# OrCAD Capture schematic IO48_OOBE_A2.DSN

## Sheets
1 01. Title: title: HPS IO48 OOBE Daughter Card; rev: A2; note: 150-0330632-A2     (6XX-44479R)
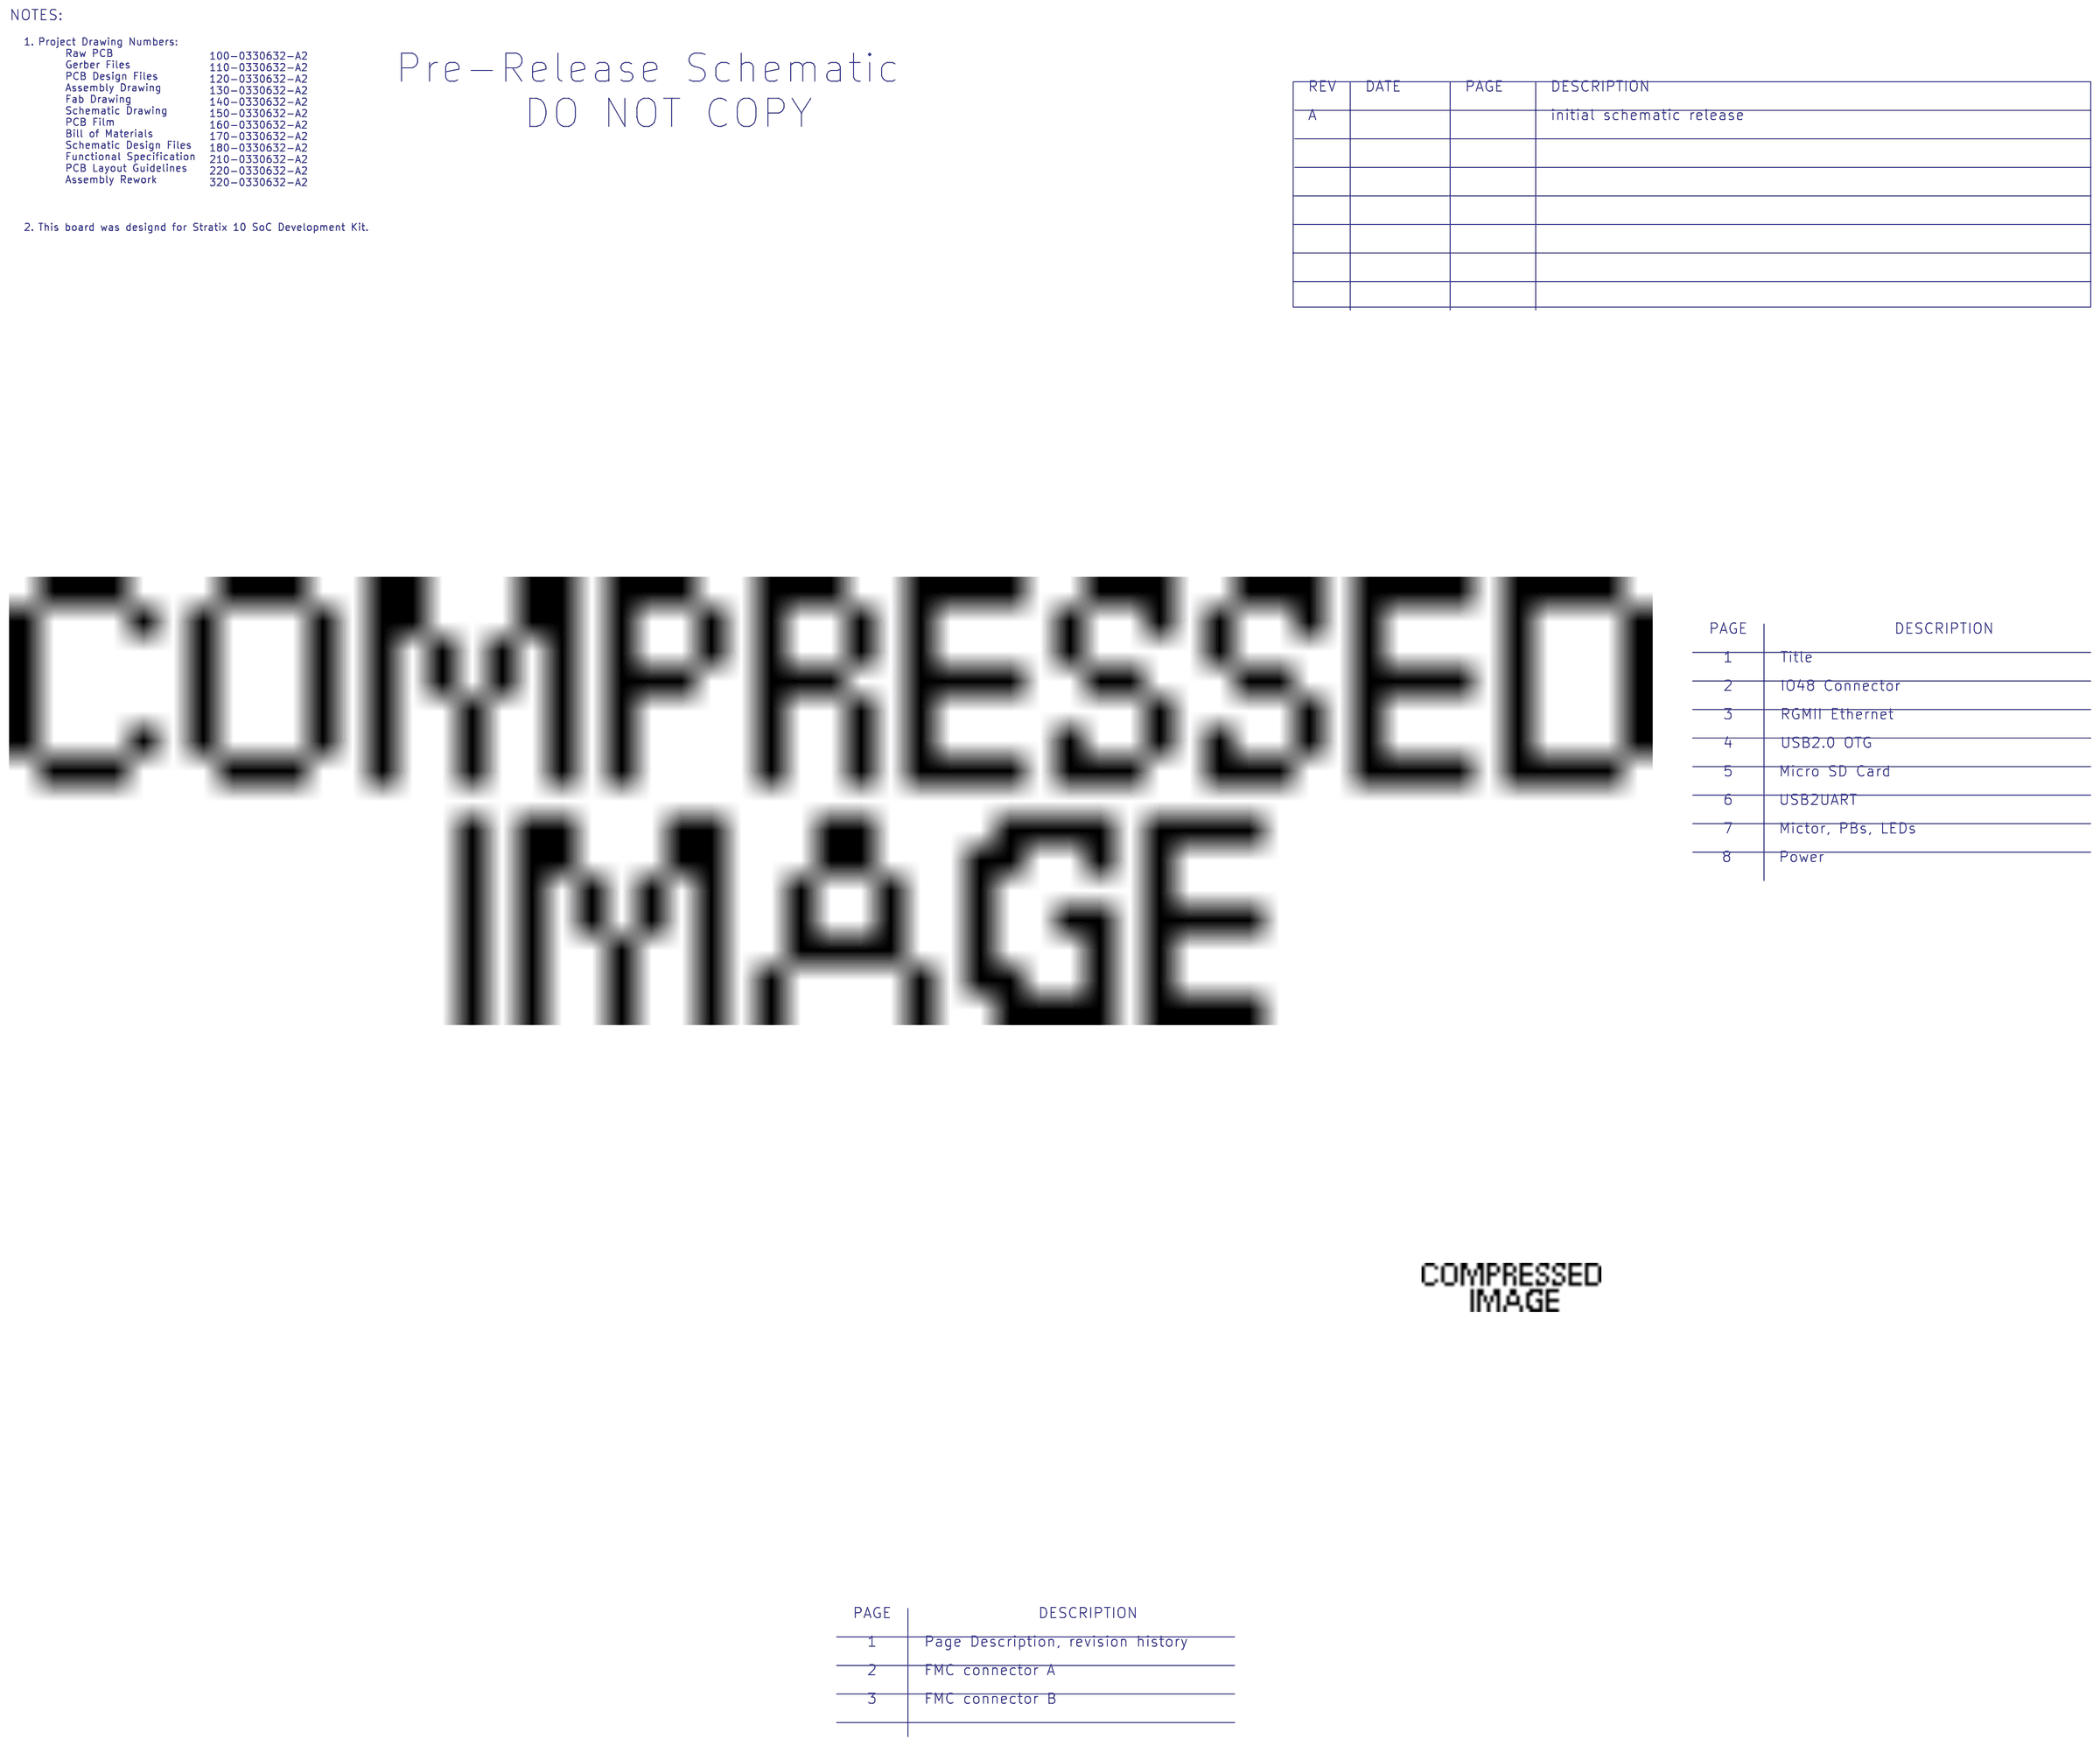
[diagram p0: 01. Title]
2 02. IO48 Connector: size B
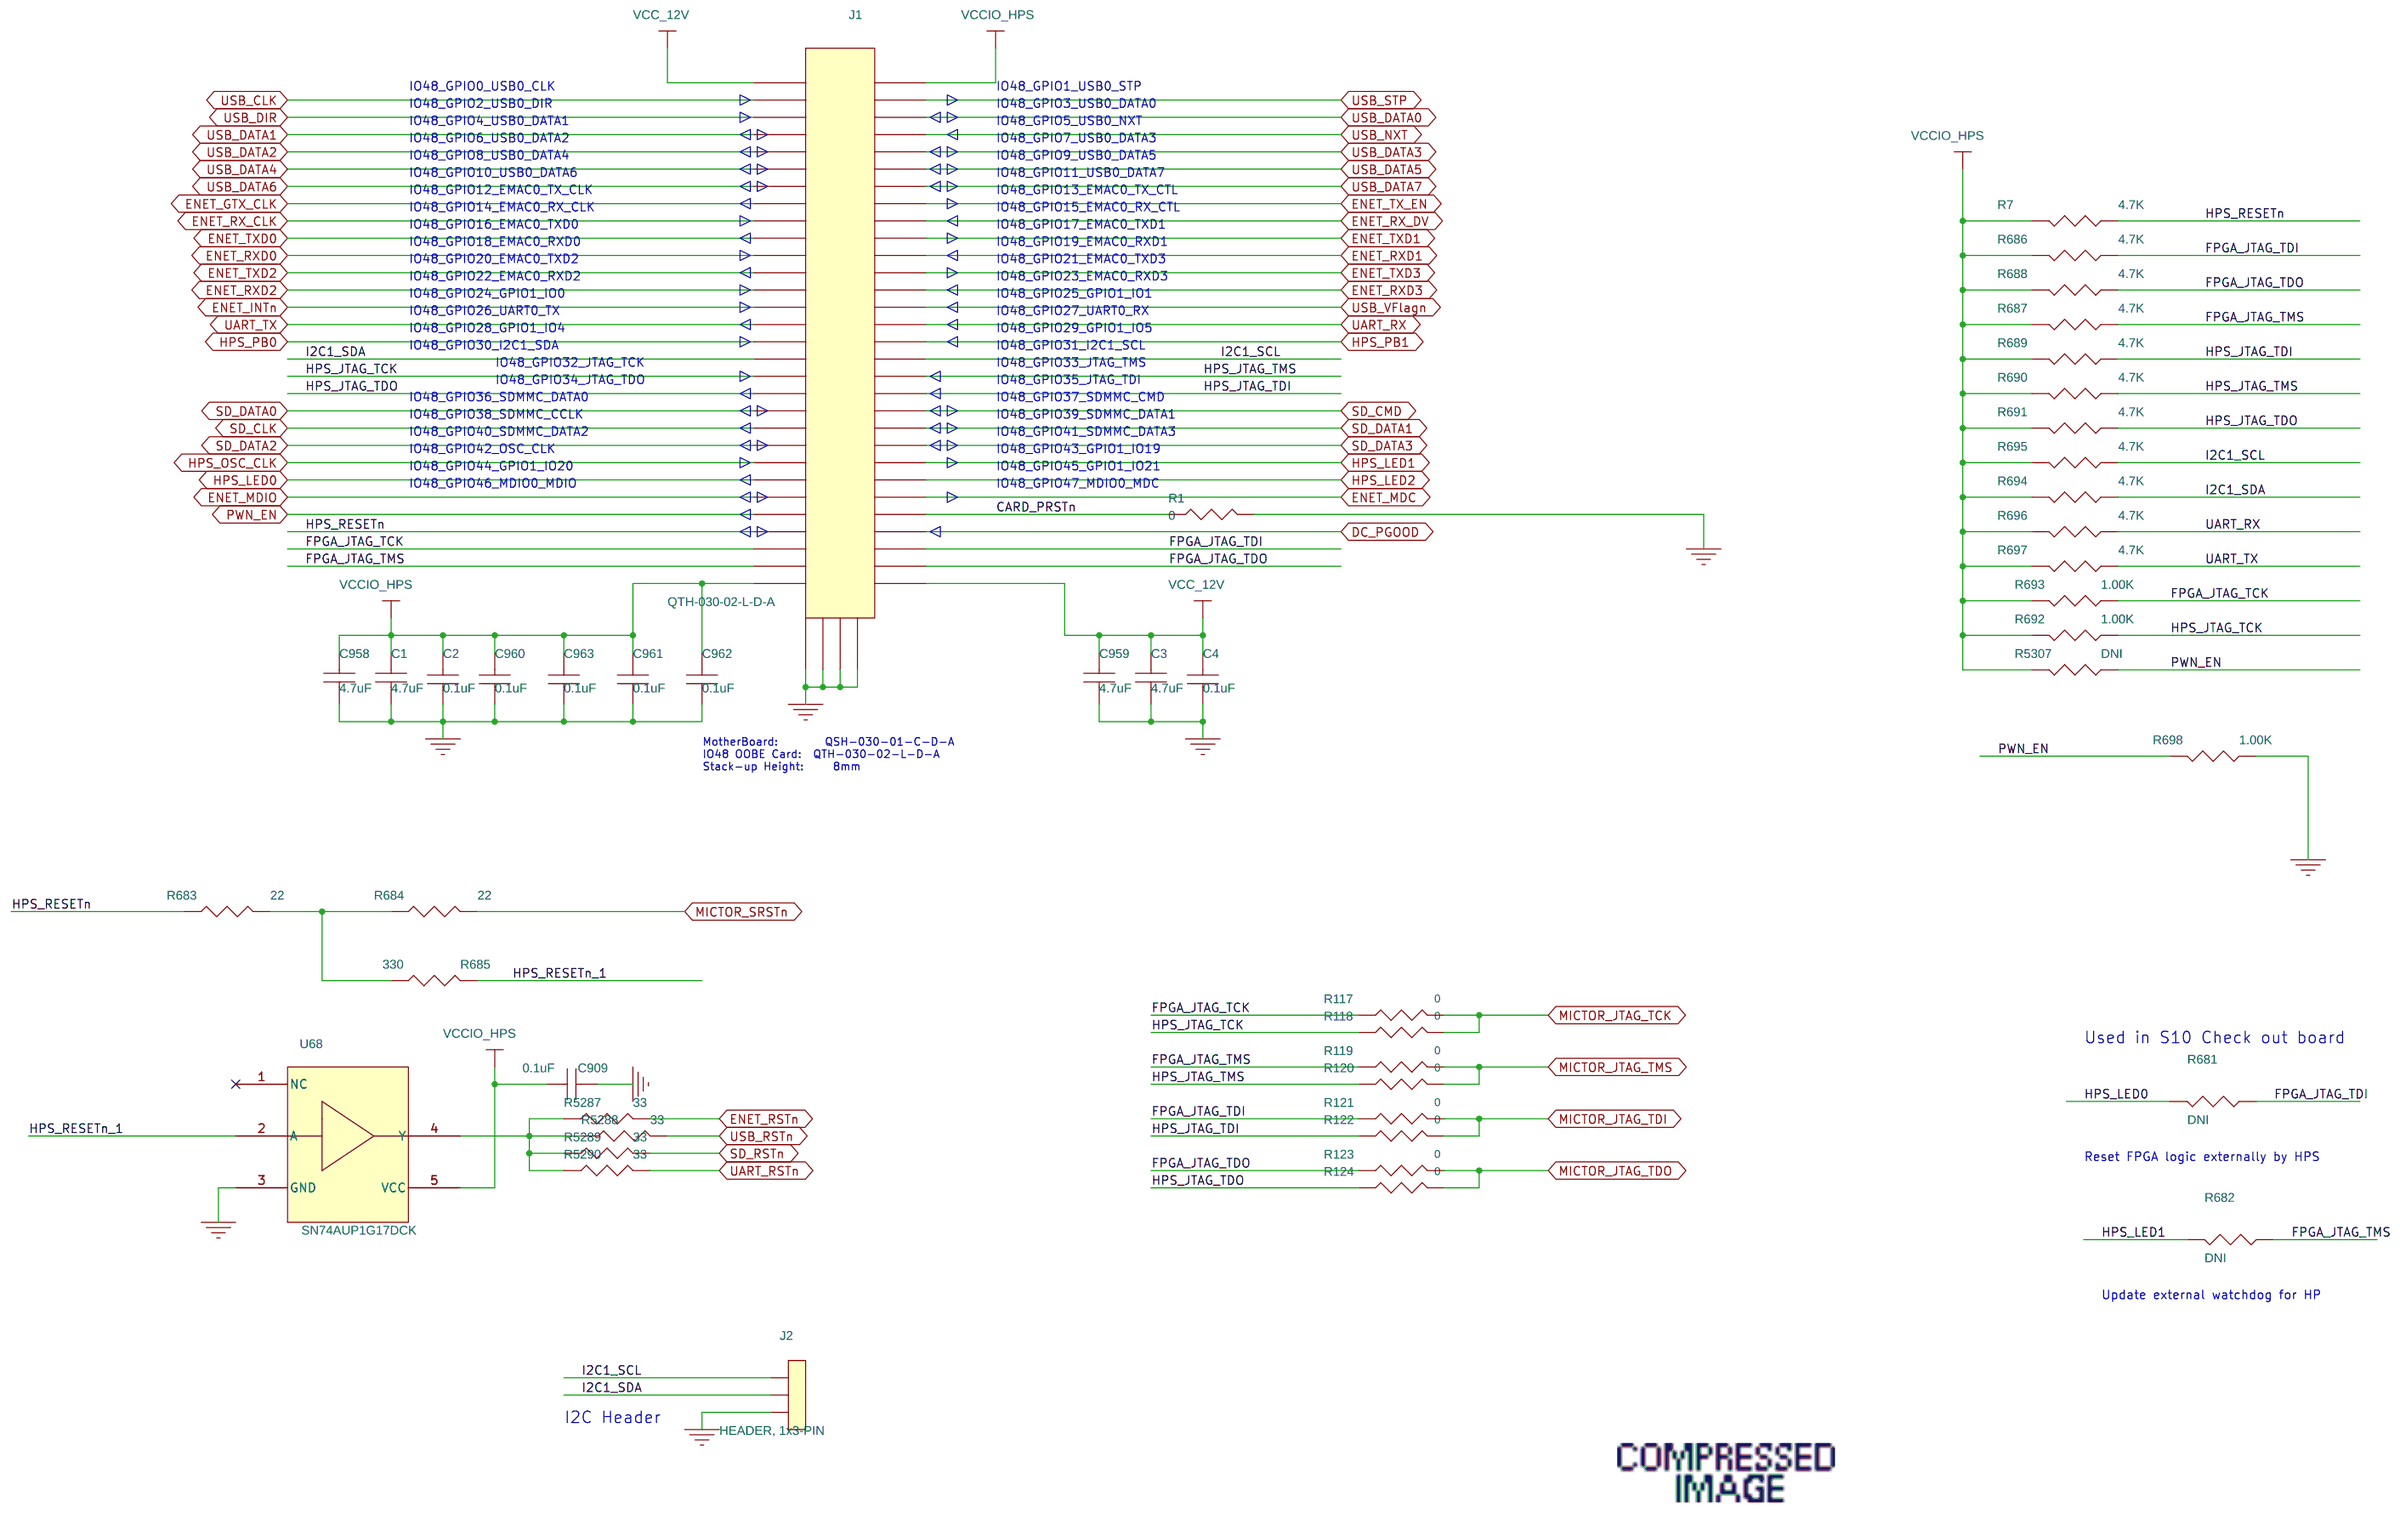
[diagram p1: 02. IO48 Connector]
3 03. RGMII Ethernet: size B
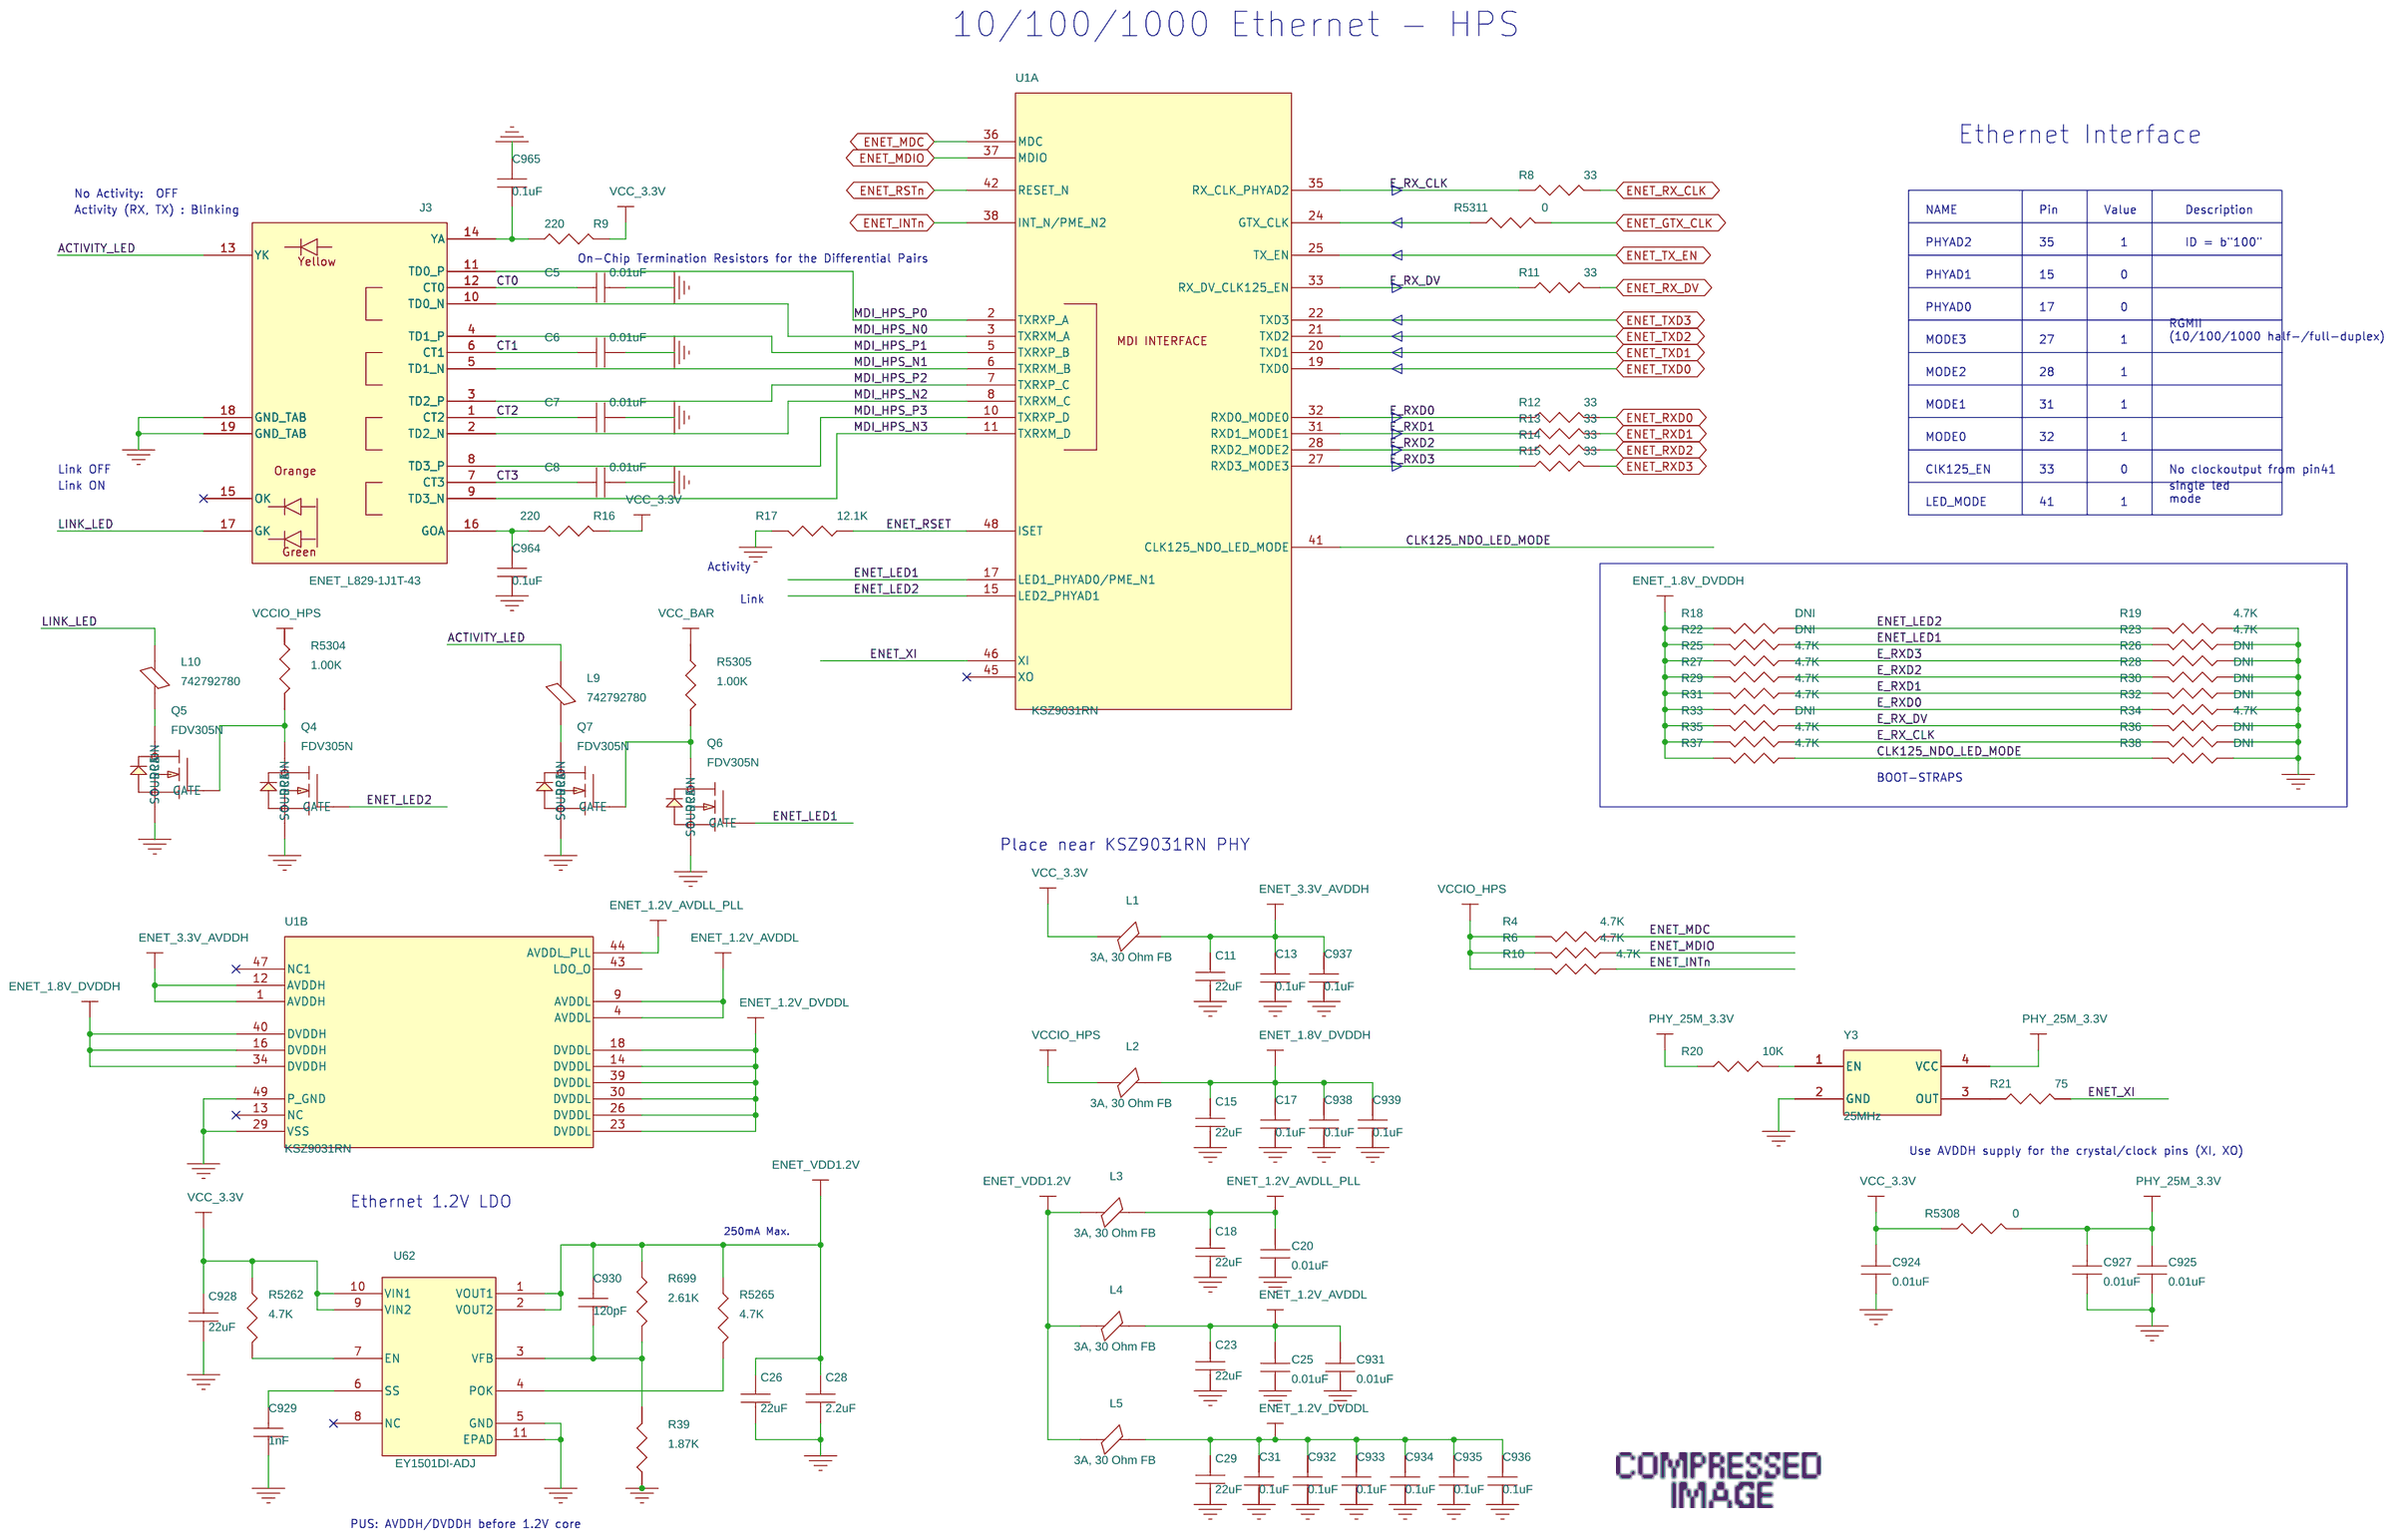
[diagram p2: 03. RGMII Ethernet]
4 04. USB2.0 OTG: size B
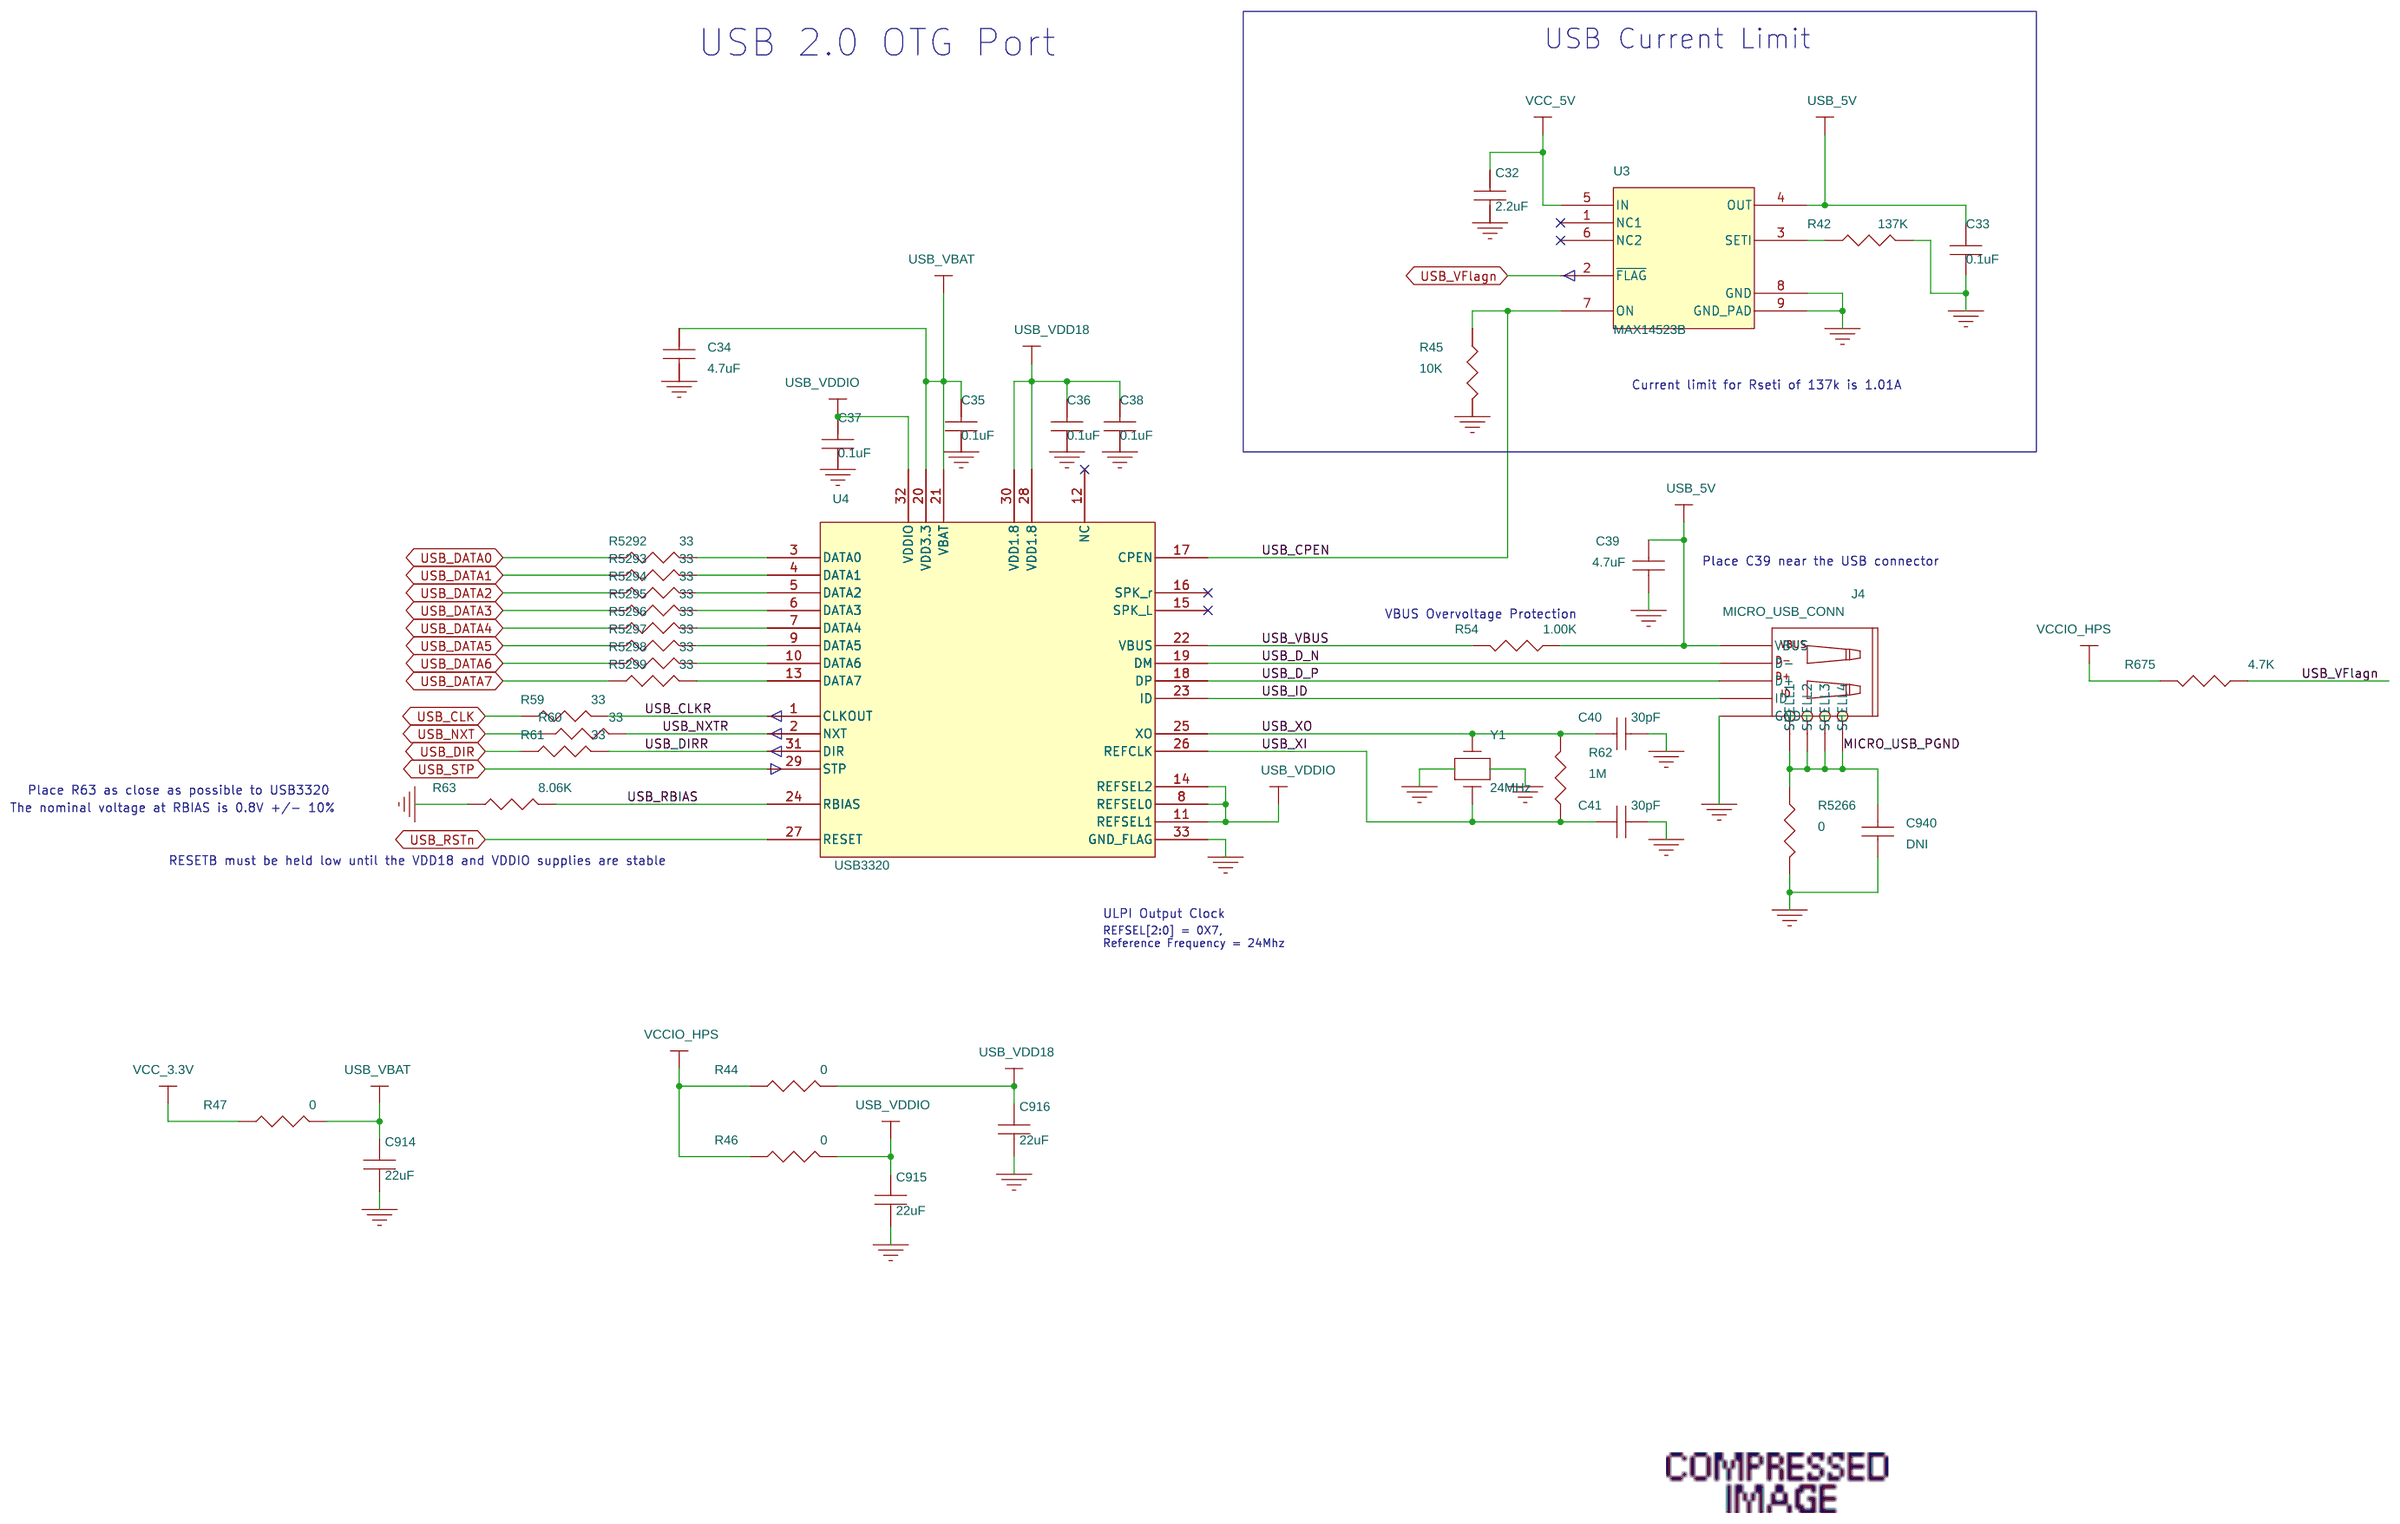
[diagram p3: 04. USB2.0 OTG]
5 05. Micro SD Card: size B
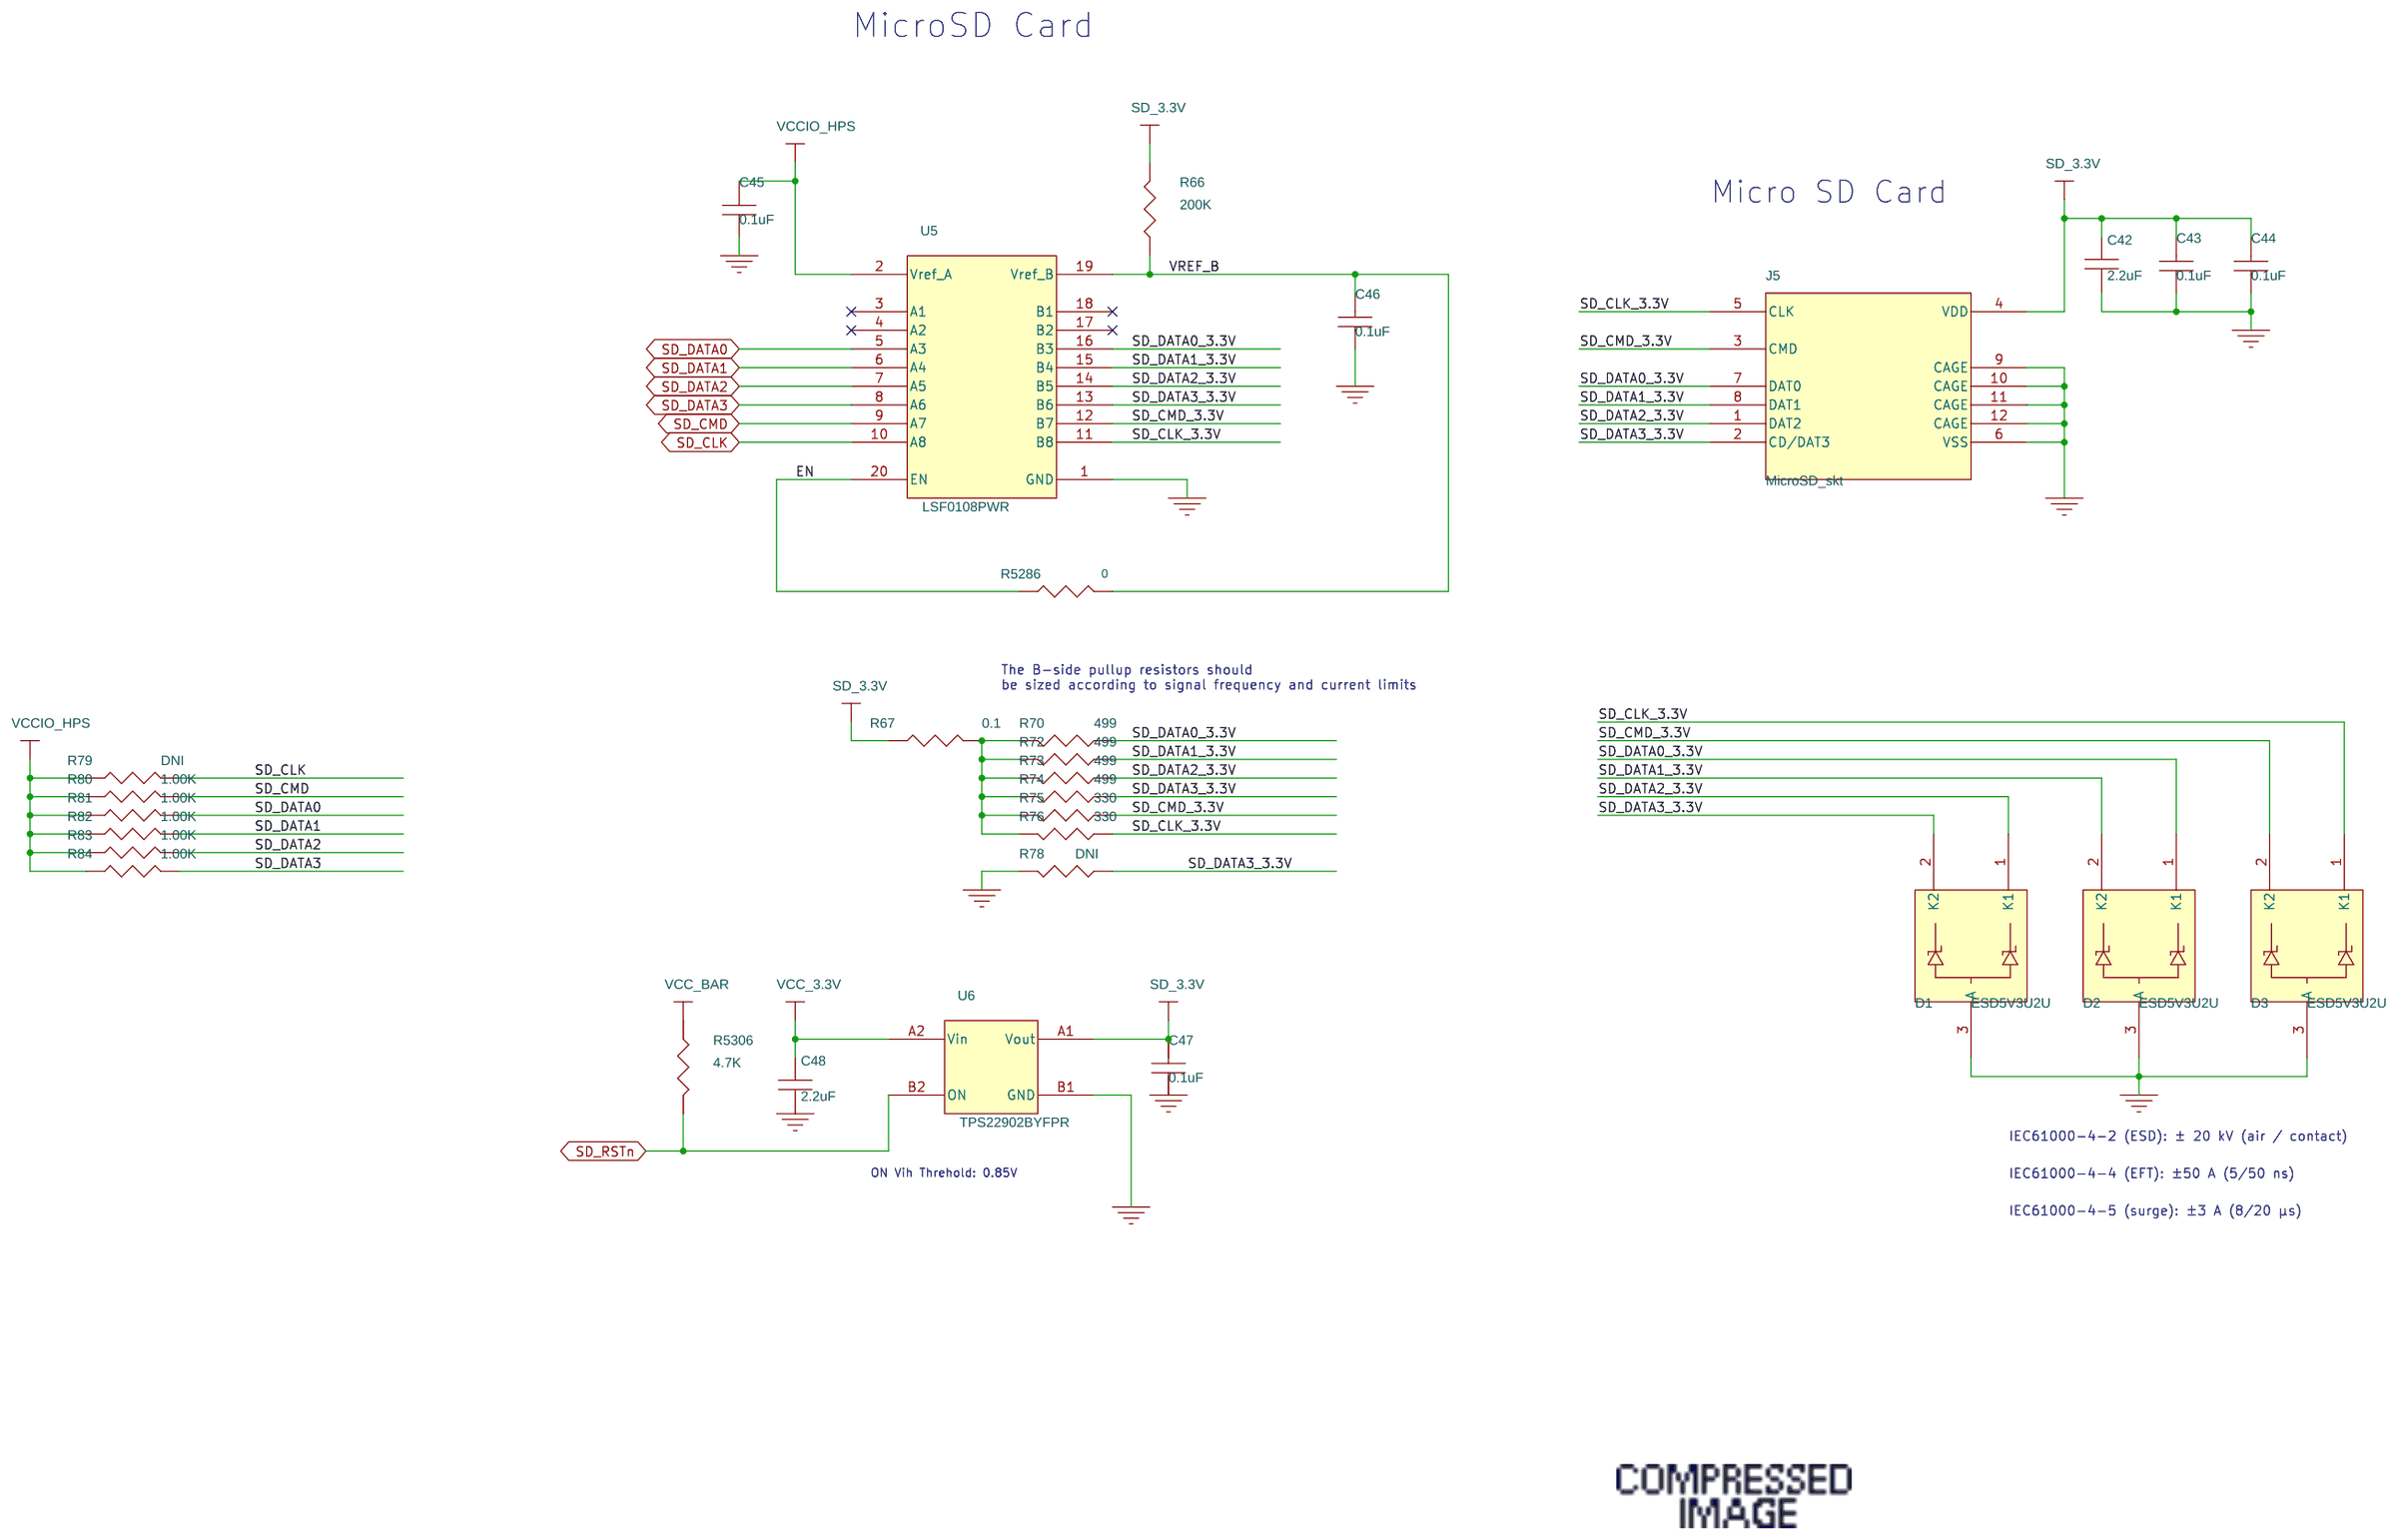
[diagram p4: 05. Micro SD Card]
6 06. USB2UART: size B
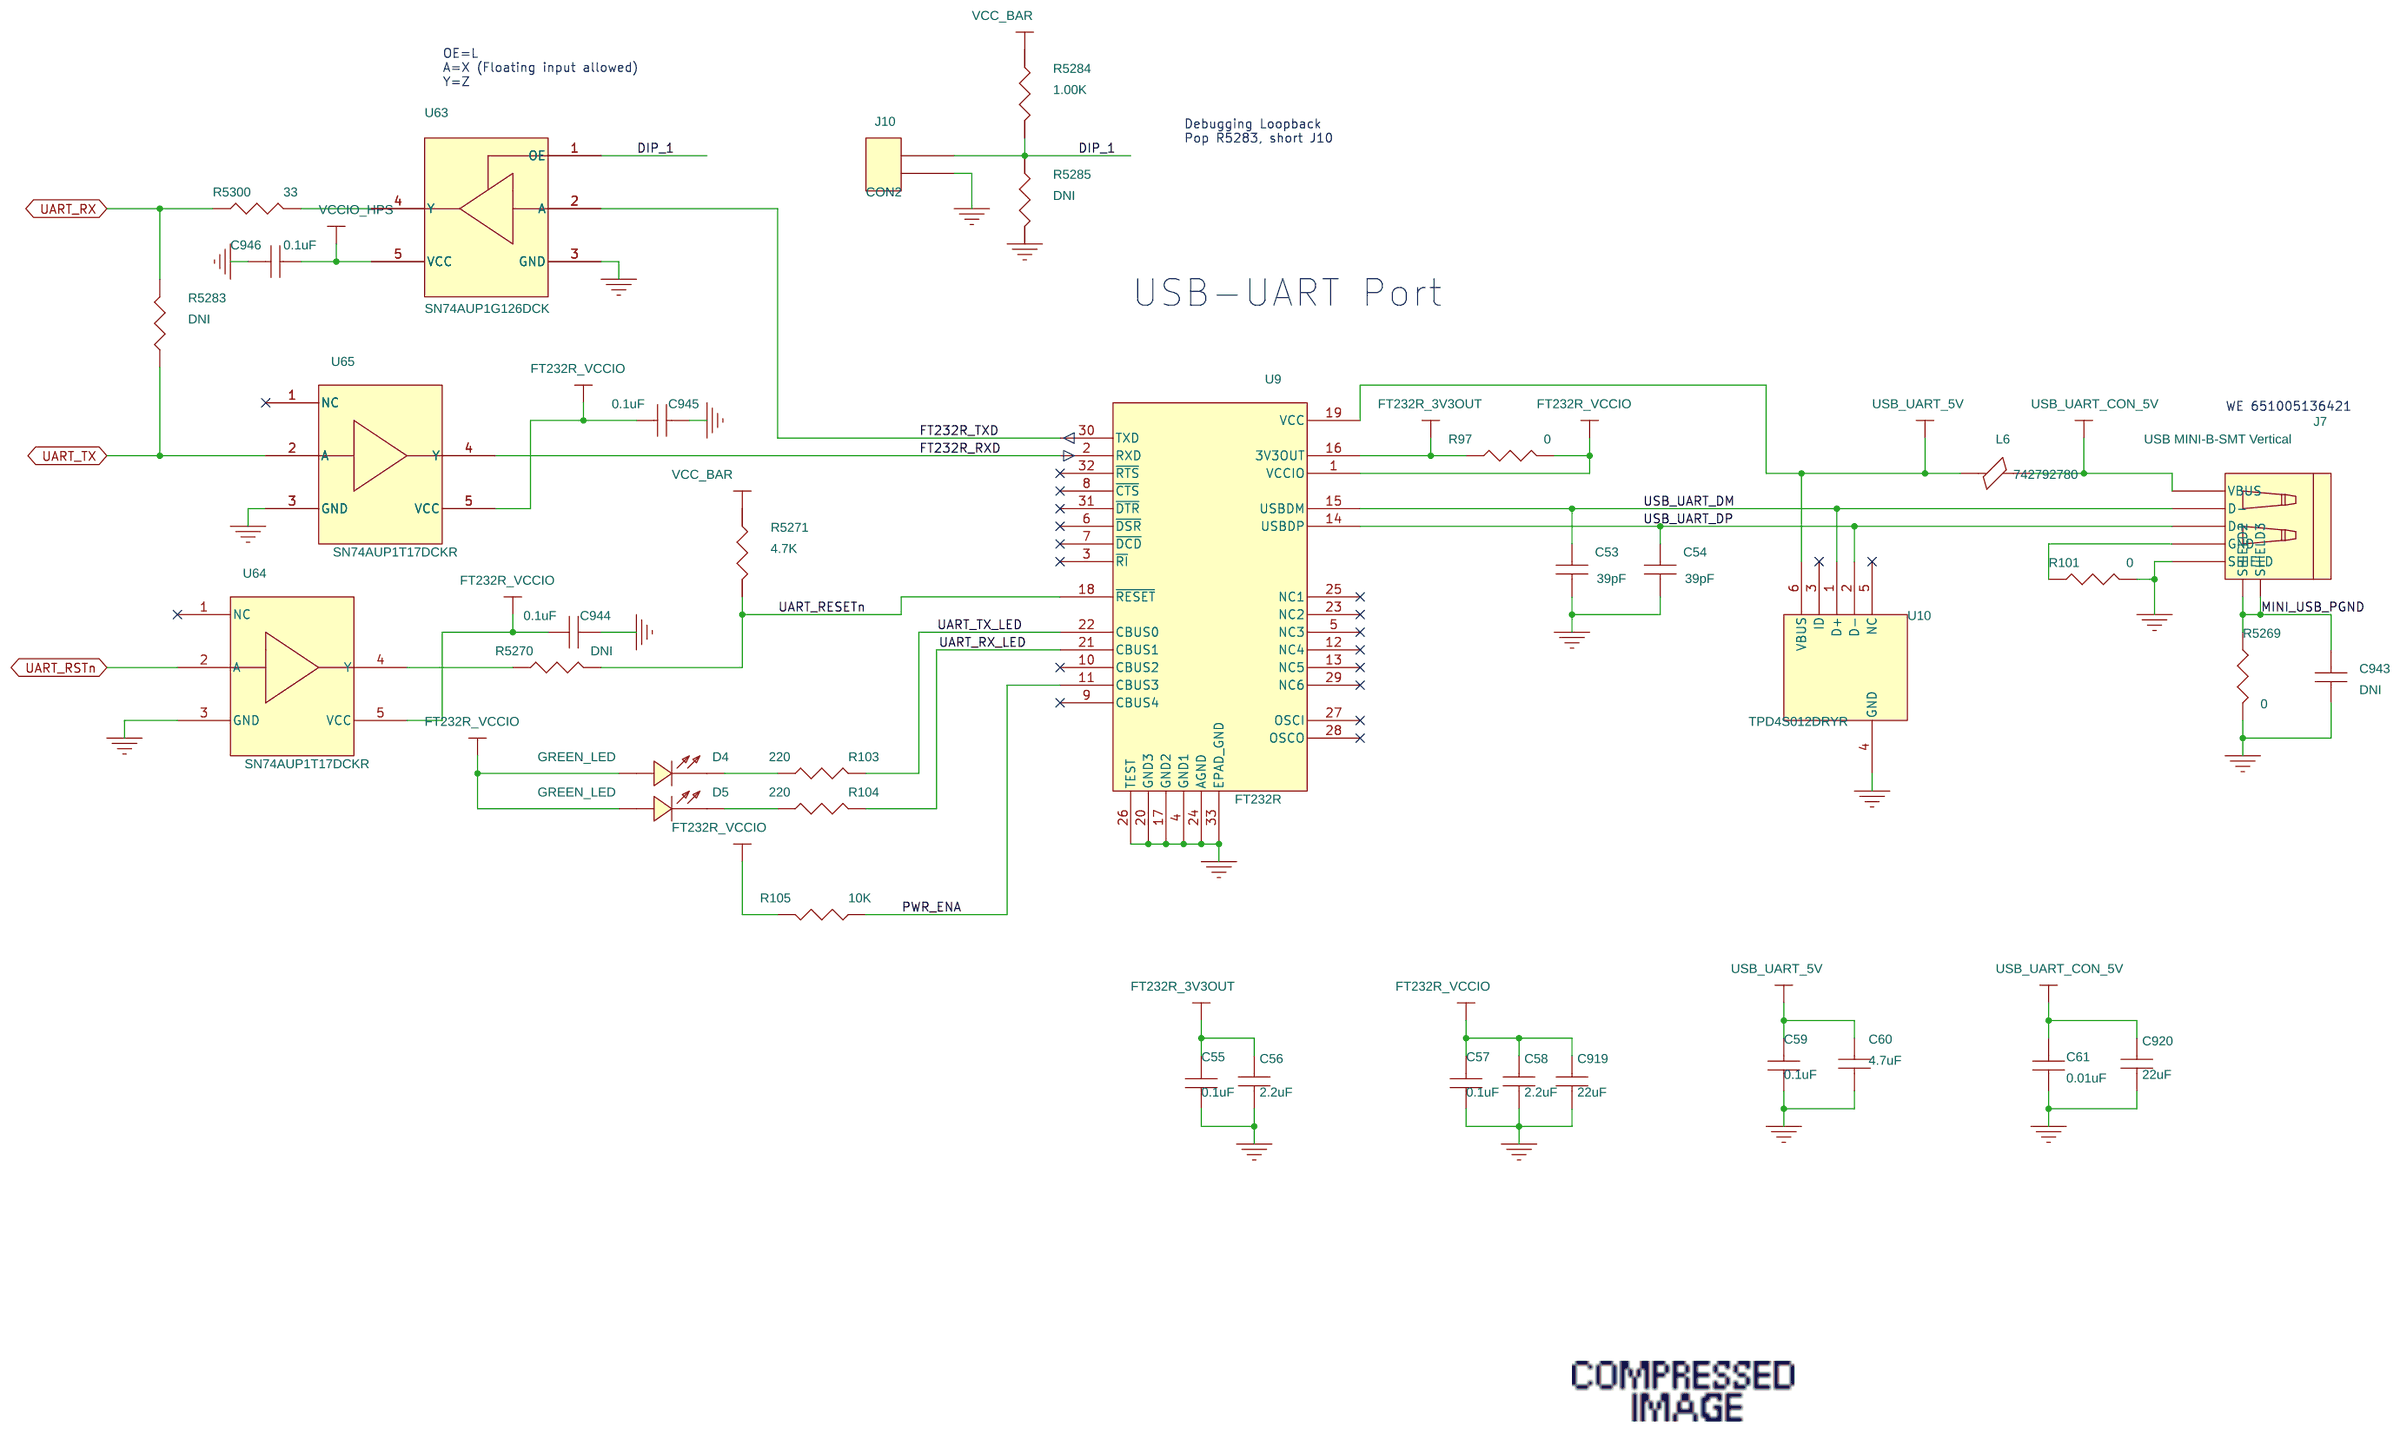
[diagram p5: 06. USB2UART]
7 07. Mictor, PBs, LEDs: size B
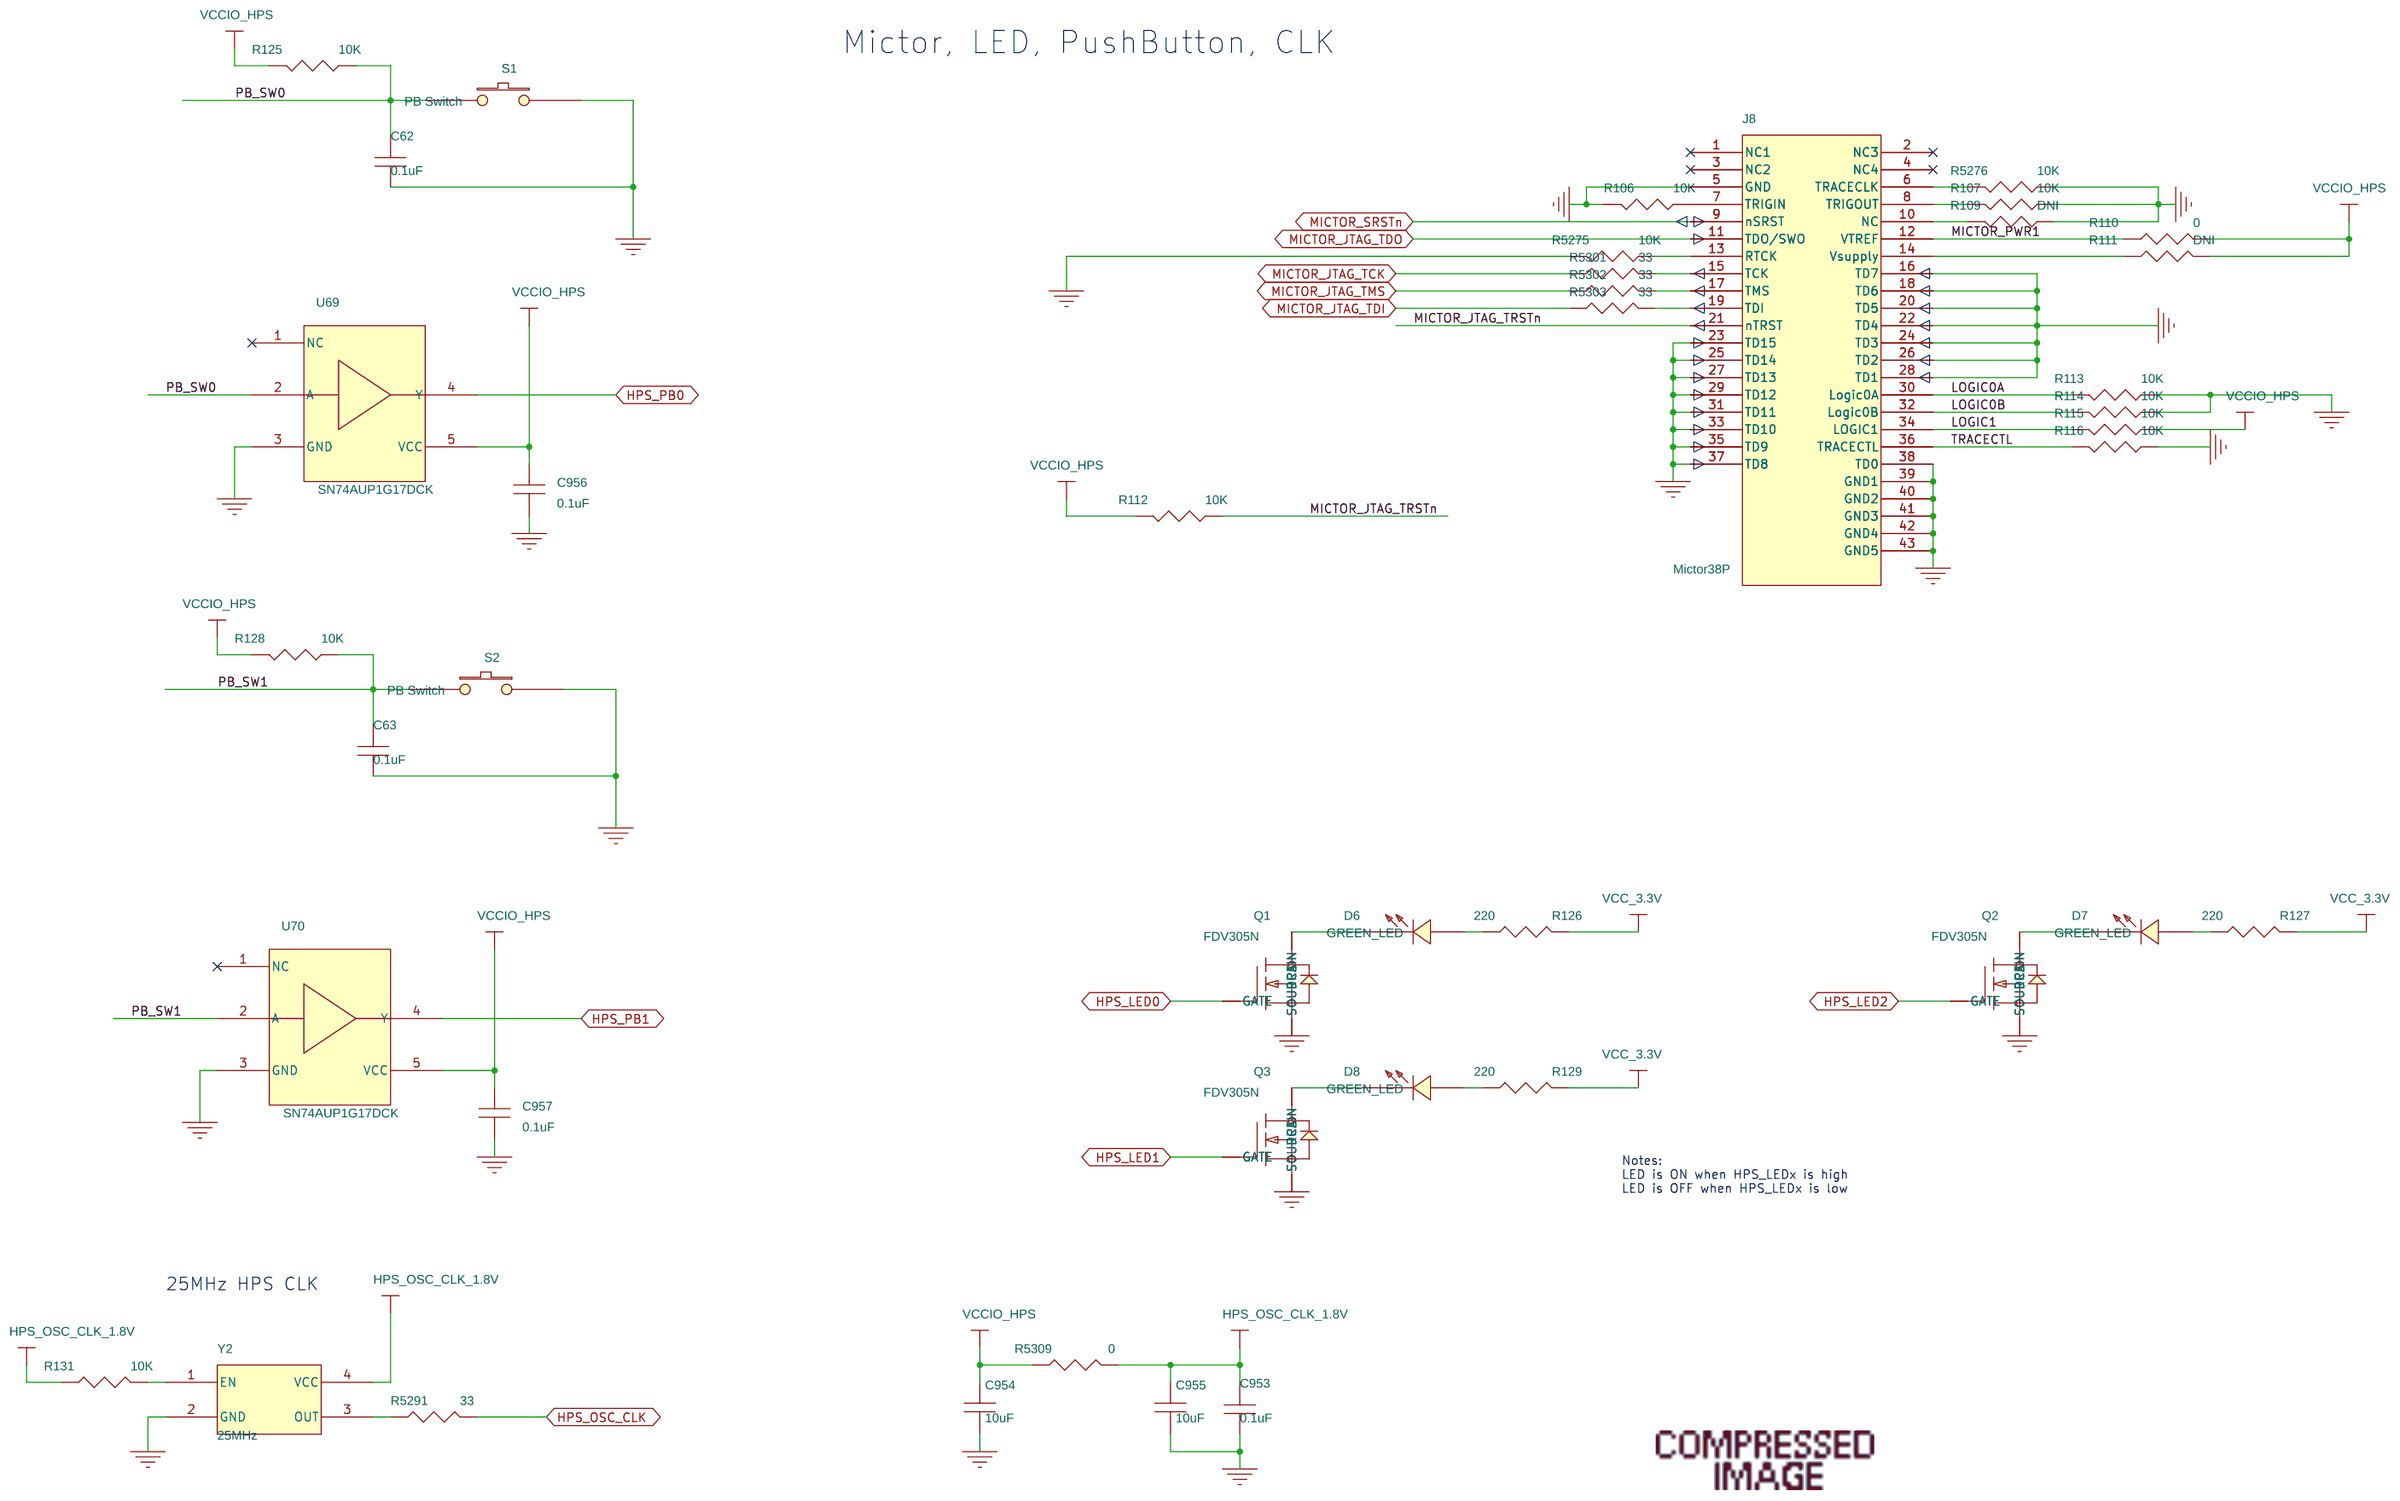
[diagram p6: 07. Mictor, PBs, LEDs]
8 08. Power: size B
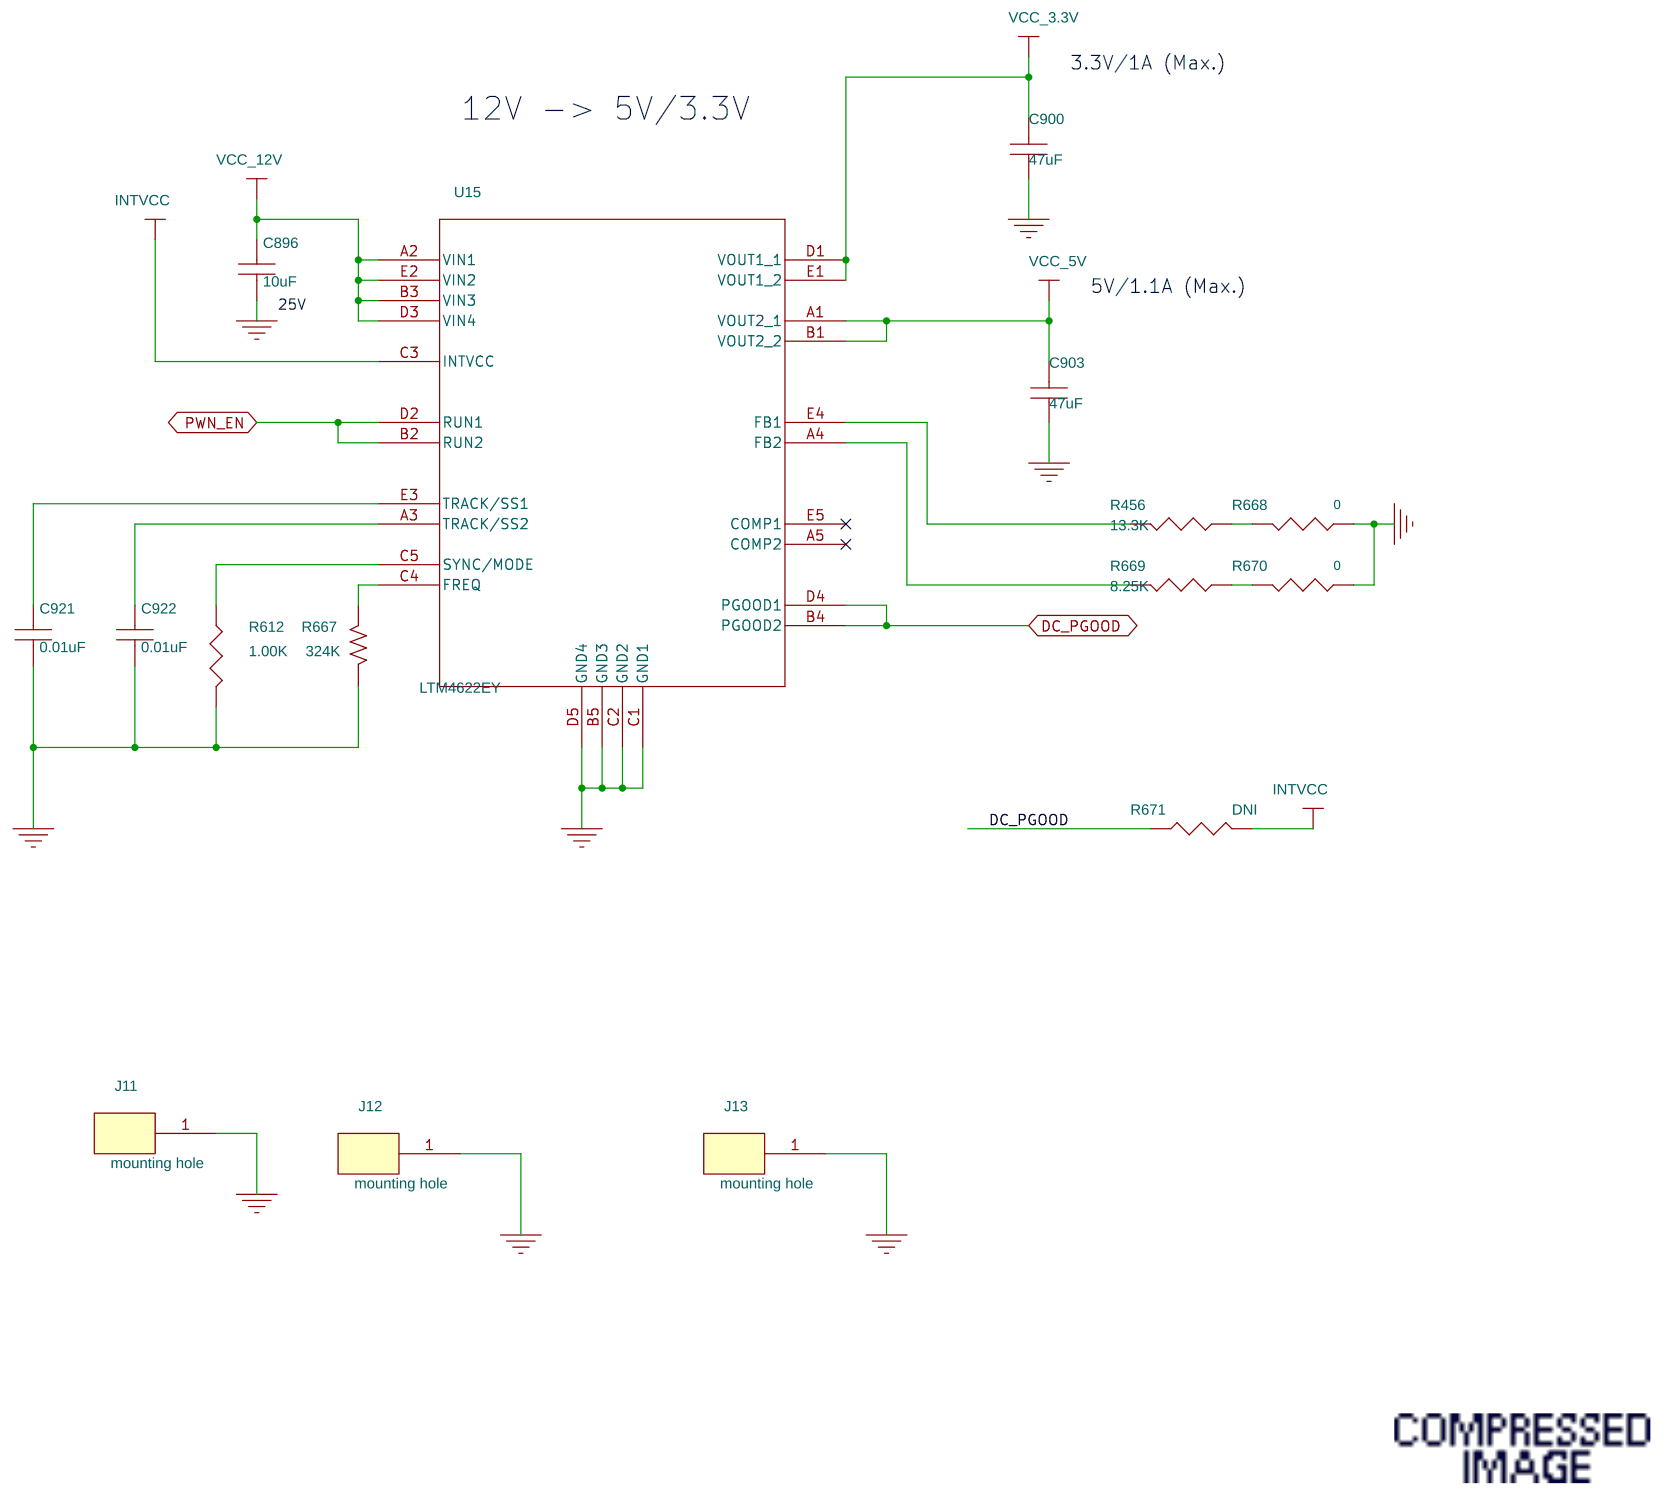
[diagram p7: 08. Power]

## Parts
sheet 02. IO48 Connector
C1  4.7uF  [0805]
C2  0.1uF  [0402]
C3  4.7uF  [0805]
C4  0.1uF  [0402]
C909  0.1uF  [0402]
C958  4.7uF  [0805]
C959  4.7uF  [0805]
C960  0.1uF  [0402]
C961  0.1uF  [0402]
C962  0.1uF  [0402]
C963  0.1uF  [0402]
J1  QTH-030-02-L-D-A  [QTH-030]
J2  HEADER, 1x3-PIN  [CONN_TSW_103_07_L_S]
R1  0  [0402]
R7  4.7K  [0402]
R117  0  [0402]
R118  0  [0402]
R119  0  [0402]
R120  0  [0402]
R121  0  [0402]
R122  0  [0402]
R123  0  [0402]
R124  0  [0402]
R681  DNI  [0402]
R682  DNI  [0402]
R683  22  [0402]
R684  22  [0402]
R685  330  [0402]
R686  4.7K  [0402]
R687  4.7K  [0402]
R688  4.7K  [0402]
R689  4.7K  [0402]
R690  4.7K  [0402]
R691  4.7K  [0402]
R692  1.00K  [0402]
R693  1.00K  [0402]
R694  4.7K  [0402]
R695  4.7K  [0402]
R696  4.7K  [0402]
R697  4.7K  [0402]
R698  1.00K  [0402]
R5287  33  [0402]
R5288  33  [0402]
R5289  33  [0402]
R5290  33  [0402]
R5307  DNI  [0402]
U68  SN74AUP1G17DCK  [SC70_TI]
sheet 03. RGMII Ethernet
C5  0.01uF  [0402]
C6  0.01uF  [0402]
C7  0.01uF  [0402]
C8  0.01uF  [0402]
C11  22uF  [0603]
C13  0.1uF  [0402]
C15  22uF  [0603]
C17  0.1uF  [0402]
C18  22uF  [0603]
C20  0.01uF  [0402]
C23  22uF  [0603]
C25  0.01uF  [0402]
C26  22uF  [0603]
C28  2.2uF  [0603]
C29  22uF  [0603]
C31  0.1uF  [0402]
C924  0.01uF  [0402]
C925  0.01uF  [0402]
C927  0.01uF  [0402]
C928  22uF  [0603]
C929  1nF  [0402]
C930  120pF  [0402]
C931  0.01uF  [0402]
C932  0.1uF  [0402]
C933  0.1uF  [0402]
C934  0.1uF  [0402]
C935  0.1uF  [0402]
C936  0.1uF  [0402]
C937  0.1uF  [0402]
C938  0.1uF  [0402]
C939  0.1uF  [0402]
C964  0.1uF  [0402]
C965  0.1uF  [0402]
J3  ENET_L829-1J1T-43  [bel_l829-1j1t-43]
L1  3A, 30 Ohm FB  [ind_0603]
L2  3A, 30 Ohm FB  [ind_0603]
L3  3A, 30 Ohm FB  [ind_0603]
L4  3A, 30 Ohm FB  [ind_0603]
L5  3A, 30 Ohm FB  [ind_0603]
L9  742792780  [0402]
L10  742792780  [0402]
Q4  FDV305N  [SOT23]
Q5  FDV305N  [SOT23]
Q6  FDV305N  [SOT23]
Q7  FDV305N  [SOT23]
R4  4.7K  [0402]
R6  4.7K  [0402]
R8  33  [0402]
R9  220  [0402]
R10  4.7K  [0402]
R11  33  [0402]
R12  33  [0402]
R13  33  [0402]
R14  33  [0402]
R15  33  [0402]
R16  220  [0402]
R17  12.1K  [0402]
R18  DNI  [0402]
R19  4.7K  [0402]
R20  10K  [0402]
R21  75  [0402]
R22  DNI  [0402]
R23  4.7K  [0402]
R25  4.7K  [0402]
R26  DNI  [0402]
R27  4.7K  [0402]
R28  DNI  [0402]
R29  4.7K  [0402]
R30  DNI  [0402]
R31  4.7K  [0402]
R32  DNI  [0402]
R33  DNI  [0402]
R34  4.7K  [0402]
R35  4.7K  [0402]
R36  DNI  [0402]
R37  4.7K  [0402]
R38  DNI  [0402]
R39  1.87K  [0402]
R699  2.61K  [0402]
R5262  4.7K  [0402]
R5265  4.7K  [0402]
R5304  1.00K  [0402]
R5305  1.00K  [0402]
R5308  0  [0402]
R5311  0  [0402]
U1  KSZ9031RN  [QFN48]  (sections A,B)
U62  EY1501DI-ADJ  [DFN-10]
Y3  25MHz  [OSC7050]
sheet 04. USB2.0 OTG
C32  2.2uF  [0603]
C33  0.1uF  [0402]
C34  4.7uF  [0805]
C35  0.1uF  [0402]
C36  0.1uF  [0402]
C37  0.1uF  [0402]
C38  0.1uF  [0402]
C39  4.7uF  [0805]
C40  30pF  [0402]
C41  30pF  [0402]
C914  22uF  [0603]
C915  22uF  [0603]
C916  22uF  [0603]
C940  DNI  [1808]
J4  MICRO_USB_CONN  [molex-micro-usb-47589-001]
R42  137K  [0402]
R44  0  [0603]
R45  10K  [0402]
R46  0  [0603]
R47  0  [0603]
R54  1.00K  [0603]
R59  33  [0402]
R60  33  [0402]
R61  33  [0402]
R62  1M  [0402]
R63  8.06K  [0402]
R675  4.7K  [0402]
R5266  0  [1206]
R5292  33  [0402]
R5293  33  [0402]
R5294  33  [0402]
R5295  33  [0402]
R5296  33  [0402]
R5297  33  [0402]
R5298  33  [0402]
R5299  33  [0402]
U3  MAX14523B  [TDFN-8]
U4  USB3320  [QFN32]
Y1  24MHz  [xtal_ecx-32]
sheet 05. Micro SD Card
C42  2.2uF  [0603]
C43  0.1uF  [0402]
C44  0.1uF  [0402]
C45  0.1uF  [0402]
C46  0.1uF  [0402]
C47  0.1uF  [0402]
C48  2.2uF  [0603]
D1  ESD5V3U2U  [TSLP-3-7]
D2  ESD5V3U2U  [TSLP-3-7]
D3  ESD5V3U2U  [TSLP-3-7]
J5  MicroSD_skt  [WURTH_MICRO-SD_CARD]
R66  200K  [0402]
R67  0.1  [0805]
R70  499  [0603]
R72  499  [0603]
R73  499  [0603]
R74  499  [0603]
R75  330  [0603]
R76  330  [0603]
R78  DNI  [0402]
R79  DNI  [0402]
R80  1.00K  [0402]
R81  1.00K  [0402]
R82  1.00K  [0402]
R83  1.00K  [0402]
R84  1.00K  [0402]
R5286  0  [0402]
R5306  4.7K  [0402]
U5  LSF0108PWR  [tssop20]
U6  TPS22902BYFPR  [TPS22902BYFPR]
sheet 06. USB2UART
C53  39pF  [0402]
C54  39pF  [0402]
C55  0.1uF  [0402]
C56  2.2uF  [0603]
C57  0.1uF  [0402]
C58  2.2uF  [0603]
C59  0.1uF  [0402]
C60  4.7uF  [0805]
C61  0.01uF  [0402]
C919  22uF  [0603]
C920  22uF  [0603]
C943  DNI  [1808]
C944  0.1uF  [0402]
C945  0.1uF  [0402]
C946  0.1uF  [0402]
D4  GREEN_LED  [LED_0603]
D5  GREEN_LED  [LED_0603]
J7  USB MINI-B-SMT Vertical  [MINI_USB_SMTB]
J10  CON2  [HDR2x1_100MIL]
L6  742792780  [0402]
R97  0  [0402]
R101  0  [0402]
R103  220  [0402]
R104  220  [0402]
R105  10K  [0402]
R5269  0  [1206]
R5270  DNI  [0402]
R5271  4.7K  [0402]
R5283  DNI  [0402]
R5284  1.00K  [0402]
R5285  DNI  [0402]
R5300  33  [0402]
U9  FT232R  [Qfn32-ftdi]
U10  TPD4S012DRYR  [SON6]
U63  SN74AUP1G126DCK  [SC70_TI]
U64  SN74AUP1T17DCKR  [SC70_TI]
U65  SN74AUP1T17DCKR  [SC70_TI]
sheet 07. Mictor, PBs, LEDs
C62  0.1uF  [0402]
C63  0.1uF  [0402]
C953  0.1uF  [0402]
C954  10uF  [C0805]
C955  10uF  [C0805]
C956  0.1uF  [0402]
C957  0.1uF  [0402]
D6  GREEN_LED  [LED_0603]
D7  GREEN_LED  [LED_0603]
D8  GREEN_LED  [LED_0603]
J8  Mictor38P  [SMT38]
Q1  FDV305N  [SOT23]
Q2  FDV305N  [SOT23]
Q3  FDV305N  [SOT23]
R106  10K  [0402]
R107  10K  [0402]
R109  DNI  [0402]
R110  0  [0603]
R111  DNI  [0603]
R112  10K  [0402]
R113  10K  [0402]
R114  10K  [0402]
R115  10K  [0402]
R116  10K  [0402]
R125  10K  [0402]
R126  220  [0402]
R127  220  [0402]
R128  10K  [0402]
R129  220  [0402]
R131  10K  [0402]
R5275  10K  [0402]
R5276  10K  [0402]
R5291  33  [0402]
R5301  33  [0402]
R5302  33  [0402]
R5303  33  [0402]
R5309  0  [0402]
S1  PB Switch  [WURTH_6X3P5_TACT_SWITCH]
S2  PB Switch  [WURTH_6X3P5_TACT_SWITCH]
U69  SN74AUP1G17DCK  [SC70_TI]
U70  SN74AUP1G17DCK  [SC70_TI]
Y2  25MHz  [OSC3250]
sheet 08. Power
C896  10uF  [1206]
C900  47uF  [1206]
C903  47uF  [1206]
C921  0.01uF  [0402]
C922  0.01uF  [0402]
J11  mounting hole  [C635TC317-01]
J12  mounting hole  [C635TC317-01]
J13  mounting hole  [C635TC317-01]
R456  13.3K  [0402]
R612  1.00K  [0402]
R667  324K  [R0402]
R668  0  [0402]
R669  8.25K  [0402]
R670  0  [0402]
R671  DNI  [0402]
U15  LTM4622EY  [BGA25]

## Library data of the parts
C1 C3 C34 C39 C60 C958 C959 = CAP: CAP - CER, 4.7UF, 16V, X5R, 0805; Item Num: P03-15412R; Manufacturer: Murata; Manufacturer Part Num: GRM21BR61C475KA88L; Num Pins: 2; RoHS Compliant: RoHS Compliant
C2 C4 C13 C17 C31 C62 C63 C932-C939 C953 C960-C965 = CAP: CAP CER 0.1UF 25V 20% X7R 0402; Item Num: P03-17618R; LIFECYCLE_PHASE: Active; Manufacturer: TDK Electronics; Manufacturer Part Num: C1005X7R1E104M; Price: 0; RoHS Compliant: RoHS Compliant
C33 C35-C38 C43-C47 C55 C57 C59 C909 C944-C946 = CAP: CAP - 0.1UF 0402 25V X7R; Item Num: P03-17618R; Manufacturer: TDK Electronics; Manufacturer Part Num: C1005X7R1E104M; RoHS Compliant: RoHS Compliant
J1 = HEADER_30X2_0: 60 PIN HIGH SPEED GROUND PLANE HEARDER; Item Num: P23-38641R; Manufacturer: Samtec
J2 = HEADER,_1x3-PIN: CONN HEADER 3 POS 2.54MM, THROUGH HOLE; Item Num: P23-38703R; Manufacturer: Wurth Electronics; Manufacturer Part Num: 61300311121
R1 R668 R670 = RESISTOR: RES ZERO OHM 1/16W 5% 0402 SMD; Item Num: P02-14020R; Manufacturer: Panasonic; Manufacturer Part Num: ERJ-2GE0R00X; RoHS Compliant: RoHS Compliant
R4 R6 R7 R10 R18 R22 R25-R34 R36 R37 R675 R686-R691 R694-R697 R5262 R5265 R5306 = RESISTOR: RES,4.70K OHMS,1.0%,1/16W,0402; Item Num: P02-11384R; LIFECYCLE_PHASE: Active; Manufacturer: Vishay; Manufacturer Part Num: CRCW04024K70FKED; RoHS Compliant: RoHS Compliant
R97 R101 R117-R124 R5286 R5308 R5309 R5311 = RESISTOR: RES ZERO OHM 1/16W 5% 0402 SMD; Item Num: P02-14020R; Manufacturer: Panasonic; Manufacturer Part Num: ERJ-2GE0R00X; Num Pins: 2; RoHS Compliant: RoHS Compliant
R681 R682 = RESISTOR: RES ZERO OHM 1/16W 5% 0402 SMD; Item Num: P02-14020R; Manufacturer: Panasonic; Manufacturer Part Num: ERJ-2GE0R00X; Price: 0; RoHS Compliant: RoHS Compliant
R683 R684 = RESISTOR: RES - 22.0 OHM, 1/16W, 1%, 0402 SMD; Item Num: P02-16269R; Manufacturer: Panasonic; Manufacturer Part Num: ERJ-2RKF22R0X; Part Number: P02-16269R; Tolerance: +/-1%
R685 = RESISTOR: RES SMD 330 OHM 1% 1/16W 0402; Item Num: P02-17737R; Manufacturer: Vishay Dale; Manufacturer Part Num: CRCW0402330RFKED; Num Pins: 2; Price: 0; RoHS Compliant: RoHS Compliant
R79-R84 R612 R692 R693 R698 R5284 R5304 R5305 R5307 = RESISTOR: RES,1.00KOHMS,1.0%,1/16W,0402; Item Num: P02-11372R; Manufacturer: Panasonic; Manufacturer Part Num: ERJ-2RKF1001X; Num Pins: 2; RoHS Compliant: RoHS Compliant
R8 R11-R15 R59-R61 R5287-R5303 = RESISTOR: RES 33 OHM 1/16W 5% 0402 SMD; Item Num: P02-14029R; LIFECYCLE_PHASE: Active; Manufacturer: Panasonic; Manufacturer Part Num: ERJ-2GEJ330X; RoHS Compliant: RoHS Compliant
U68-U70 = SN74AUP1G17DCK: IC - LOW-POWER SINGLE SCHMITT-TRIGGER BUFFER 0.8 V TO 3.6 V VCC; Item Num: P01-18134R; Manufacturer: Texas Instruments; Manufacturer Part Num: SN74AUP1G17DCKR; Part Number: P01-AUP1G17
C5-C8 C20 C25 C61 C924 C925 C927 C931 = CAP: CAP - CER, 10NF, 50V, +/-10%, X7R, 0402 SMD; Item Num: P03-16318R; Manufacturer: Murata; Manufacturer Part Num: GRM155R71H103KA88D; Price: 0; RoHS Compliant: RoHS Compliant
C11 C15 C18 C23 C26 C29 C914-C916 C919 C920 C928 = CAP: CAP 22UF CER 20% 6.3VDC X5R 0603 SMT; Item Num: P03-17794R; Manufacturer: Murata; Manufacturer Part Num: GRM188R60J226MEA0; Part Number: P03-17794R; Tolerance: +/-20%; Voltage: 6.3V
C28 = CAP: CAP, CERAMIC, 2.2UF, 10%, 10VDC, X5R, 0603; Item Num: P03-15213R; LIFECYCLE_PHASE: Active; Manufacturer: Murata; Manufacturer Part Num: GRM188R61A225KE34x; RoHS Compliant: RoHS Compliant
C929 = CAP: CAP - CER, 1NF, 10%, 50V, X7R, 0402; Item Num: P03-15174R; LIFECYCLE_PHASE: Active; Manufacturer: Murata; Manufacturer Part Num: GRM155R71H102KA01D; Price: 0; RoHS Compliant: RoHS Compliant
C930 = CAP: CAP - CER, 120PF, 50V, 5%, C0G, 0402; Item Num: P03-15872R; LIFECYCLE_PHASE: Active; Manufacturer: Murata; Manufacturer Part Num: GRM1555C1H121JA01D; Price: 0; RoHS Compliant: RoHS Compliant
J3 = ENET_L829-1J1T-43_2: CONN - RJ45 SINGLE PORT, 1000BASE-T GIGABIT ETHERNET MAGJACK 1 X 1 WITHLEDS, LOW PROFILE; Item Num: P23-38514R; Manufacturer: Bel Stewart Connector; Manufacturer Part Num: L829-1J1T-43; RoHS Compliant: RoHS Compliant
L1-L5 = IND_Ferrite_0603_3A_30_Ohms
L6 L9 L10 = BEAD_FERRITE_SM: IND - SMD EMI FILTERS/CHIP FERRITE BEAD, 220-OHM @ 100MHZ, 0.35-OHM DCR, 0402; Item Num: P04-17068R; Manufacturer: Wurth Elektronik; Num Pins: 2; RoHS Compliant: RoHS Compliant
Q1-Q7 = NMOS_3Pin: IC, MOSFET, N-CHANNEL, 20V; DCR: 0.3; Item Num: P18-31002R; Manufacturer: Fairchild Semiconductor; Voltage: 20V
R9 R16 = RESISTOR: RES, 220 OHMS, 5%, 1/16W, 0402; Item Num: P02-14107R; Manufacturer: Panasonic; Manufacturer Part Num: ERJ-2GEJ221X; Price: 0; RoHS Compliant: RoHS Compliant
R17 = RESISTOR: RES-SMD 1/16watt 12.1Kohms 1% 0402; Item Num: P02-17669R; Manufacturer: Vishay; Manufacturer Part Num: CRCW040212K1FKED; Price: 0
R19 R23 R35 R38 = RESISTOR: RES,4.70K OHMS,1.0%,1/16W,0402; Item Num: P02-11384R; LIFECYCLE_PHASE: Active; Manufacturer: Vishay; Manufacturer Part Num: CRCW04024K70FKED
R20 R106 R107 R109 R112-R116 R125 R128 R131 R671 R5275 R5276 R5285 = RESISTOR: RES,10.0K OHMS,1.0%,1/16W, 0402; Item Num: P02-11364R; Manufacturer: Panasonic; Manufacturer Part Num: ERJ-2RKF1002X; Price: 0; RoHS Compliant: RoHS Compliant
R21 = RESISTOR: RES, 75 OHM, 5%, 1/16W, 0402; Item Num: P02-14103R; LIFECYCLE_PHASE: Active; Manufacturer: Panasonic; Manufacturer Part Num: ERJ-2GEJ750X; RoHS Compliant: RoHS Compliant
R39 = RESISTOR: RES - 1.87K OHMS, 1.0%, 1/16W, 0402; Item Num: P02-16414R; Manufacturer: Vishay; Manufacturer Part Num: CRCW04021K87FKxx; RoHS Compliant: RoHS Compliant
R699 = R: RES - 2.61K OHM, 1%,1/10W, 0402 SMD; Item Num: P02-16710R; Manufacturer: Panasonic; Manufacturer Part Num: ERJ-2RKF2611x; Price: 0; RoHS Compliant: RoHS Compliant
U1 = KSZ9031RN_4: IC- PHY 1-CH 10MBPS/100MBPS/1GBPS 48-PIN QFN; Item Num: P01-17926R; Manufacturer: Micrel Semiconductor; Manufacturer Part Num: KSZ9031RNXCA; RoHS Compliant: RoHS Compliant
U62 = EY1501DI-ADJ: IC - EY1501DI-ADJ HIGH PERFORMANCE 1A LDO; Item Num: P01-18061R; Manufacturer: Altera Corporation
Y3 = OSC_ALT: OSC - CRYSTAL OSC. LVCMOS/LVTTL 25.000 MHZ OUTPUT SMT +/-50PPM; Item Num: P13-26150R; Manufacturer: ECS, Inc.; Manufacturer Part Num: ECS-3953C-250-B
C32 C42 C48 C56 C58 = CAP: CAP, CERAMIC, 2.2UF, 10%, 10VDC, X5R, 0603; Item Num: P03-15213R; Manufacturer: Murata; Manufacturer Part Num: GRM188R61A225KE34x; RoHS Compliant: RoHS Compliant
C40 C41 = CAP: CAP,30PF,0402,16V,10%; Item Num: P03-16032R; Manufacturer: MURATA; Manufacturer Part Num: GRM1555C1H300JZ01D; Num Pins: 2; RoHS Compliant: RoHS Compliant
C940 C943 = CAP: CAP CER 1000PF 3KV X7R 1808; Item Num: P03-17908R; Manufacturer: Yageo; Manufacturer Part Num: CC1808KKX7REBB102; Num Pins: 2; RoHS Compliant: RoHS Compliant
J4 = MICRO_USB_CONN: RECEPTACLE, USB 3.0, MICRO B, R/A; Item Num: P23-38552R; Manufacturer: Molex; Manufacturer Part Num: 47589-0001; RoHS Compliant: RoHS Compliant
R42 = RES_178K_Ohm_1%_1_10W_0402: SMD 1/16WATT 137KOHMS 1% 0402; Item Num: P02-17640R; Manufacturer: Vishay; Manufacturer Part Num: CRCW0402137KFKED; RoHS Compliant: RoHS Compliant
R44 R46 R47 R110 R111 = RESISTOR: RES - 0 OHM, 5% 0603 1/10W; Item Num: P02-14007R; MFR_LIFECYCLE: Active; Manufacturer: Panasonic; Manufacturer Part Num: ERJ-3GEY0R00V; Num Pins: 2; RoHS Compliant: RoHS Compliant
R45 = RESISTOR: RES,10.0K OHMS,1.0%,1/16W, 0402; Item Num: P02-11364R; Manufacturer: Panasonic; Manufacturer Part Num: ERJ-2RKF1002X; RoHS Compliant: RoHS Compliant
R54 = RESISTOR: RES, 1K OHMS, 1%, 1/10W, 0603; Item Num: P02-14119R; Manufacturer: NIC Components Corp.; Manufacturer Part Num: NRC06F1001TRF; Num Pins: 2; RoHS Compliant: RoHS Compliant
R62 = RESISTOR: RES 1.00M OHM 1/16W 1% 0402 SMD; Item Num: P02-14034R; Manufacturer: Panasonic; Manufacturer Part Num: ERJ-2RKF1004X; RoHS Compliant: RoHS Compliant
R63 = RESISTOR: RES - 8.06K OHM, 1/16W, 1%, 0402 SMD; Item Num: P02-14729R; Manufacturer: Vishay; Manufacturer Part Num: CRCW04028K06FKED; Num Pins: 2; Price: 0; RoHS Compliant: RoHS Compliant
R5266 R5269 = RESISTOR: RES SMD 0 OHM JUMPER 1/4W 1206; Item Num: P02-17998R; Manufacturer: Yageo; Manufacturer Part Num: RC1206JR070RL; RoHS Compliant: RoHS Compliant
U3 = MAX14523B: ICS - USB ADJ. CURRENT-LIMITED SWITCH W REVERSE CURRENT PROTECTION, ACTIVE HIGH ON, 8-TDFN-EP PACKAGE; Item Num: P01-17833R; Manufacturer: Maxim; Manufacturer Part Num: MAX14523AATA+T-ND; RoHS Compliant: RoHS Compliant
U4 = USB3320: ICS - USB HOST/OTG PHY ULPI 32-QFN; Item Num: P01-17961R; Manufacturer: SMSC; Manufacturer Part Num: USB3320C-EZK; RoHS Compliant: RoHS Compliant
Y1 = CRYSTALSM_ECS: CRYSTAL - 24.000MHZ, 20PF, 3.2MM x 2.5MM SMD; Item Num: P07-19528R; Manufacturer: ECS, Inc.; Manufacturer Part Num: ECS-240-20-33-TR; RoHS Compliant: RoHS Compliant
D1-D3 = ESD_DIODE_DUAL: DIODE - ULTRA LOW CAPACITANCE ESD DIODE ARRAY; Device: D11; Item Num: P08-20821R; MFR_LIFECYCLE: Active; Manufacturer: Infineon; Manufacturer Part Num: ESD5V3U2U-03LRH E6327; RoHS Compliant: RoHS Compliant
J5 = SD_SKT_1: CONN-MICRO SD CARD SOCKET; Item Num: P23-38481R; MFR_LIFECYCLE: Active; Manufacturer: Wurth Elektroniks; Manufacturer Part Num: 693071010811; RoHS Compliant: RoHS Compliant
R66 = RESISTOR: RES - 200K OHM, 1/16W, 1%, 0402 SMD0402 SMD; Item Num: P02-15992R; Lead Free Status: No; Manufacturer: Panasonic; Manufacturer Part Num: ERJ-2RKF2003X; Num Pins: 2; Part Class: RESISTORS; Price: 0; RoHS Compliant: RoHS Compliant
R67 = RESISTOR: RES 0.1 OHM 1% 1/2W 0805 SMD; Item Num: P02-17735R; Lead Free Status: Yes; Manufacturer: Panasonic; Manufacturer Part Num: ERJ6BWFR100V; Num Pins: 2; Part Class: Resistors; Price: 0; RoHS Compliant: Yes
R70 R72-R74 = RESISTOR: RES - 499OHM, 1% 0603 1/10W; Item Num: P02-14004R; Manufacturer: Panasonic; Manufacturer Part Num: ERJ-3EKF4990V; Num Pins: 2; PART_SUBCLASS: RESISTORS; Part Class: Resistors; RoHS Compliant: Yes
R75 R76 = RESISTOR: RES - ANTI-SULFER, 330 OHM, 1%, 1/10W, 0603; Item Num: P02-16628R; Manufacturer: Panasonic; Manufacturer Part Num: ERJ-S03F3300V; Num Pins: 2; PART_SUBCLASS: RESISTORS; Part Class: Resistors; RoHS Compliant: Yes
R78 = RESISTOR: RES - 470K OHM, 1/16W, 1%, 0402 SMD; Item Num: P02-14607R; LIFECYCLE_PHASE: Active; Lead Free Status: No; Manufacturer: Vishay; Manufacturer Part Num: CRCW0402470KFKED; Num Pins: 2; RoHS Compliant: RoHS Compliant
U5 = LSF0108PWR: 8 CHANNEL BIDIRECTIONAL MULTI-VOLTAGE LEVEL TRANSLATOR; Item Num: P01-18018R; Manufacturer: TI; RoHS Compliant: RoHS Compliant
U6 = TPS22902BYFPR: Manufacturer: TI
C53 C54 = Cap_39PF_5%_50V_0402
D4-D8 = LED_WURTH: LED - BRIGHT GREEN, VF=2V, IF=0.03A, 0603; Item Num: P09-21344R; LIFECYCLE_PHASE: Active; Manufacturer: Wurth Electroniks; Manufacturer Part Num: 150060VS75000; Num Pins: 2; RoHS Compliant: RoHS Compliant
J7 = USB_MINI_B_SMT: VERTICAL MINI USB 2.0 TYPE B 5 CONTACTS; Item Num: P23-38804R; Manufacturer: Wurth Elektronik; Manufacturer Part Num: 651005136421
J10 = CON2: 2X1 .100" CENTER HEADER; Item Num: P23-38493R; Manufacturer: Wurth Elektroniks; Manufacturer Part Num: 613 002 111 21; Num Pins: 2; Price: 0; RoHS Compliant: RoHS Compliant
R103 R126 R127 R129 = RESISTOR: RES, 220 OHMS, 5%, 1/16W, 0402; Item Num: P02-14107R; Manufacturer: Panasonic; Manufacturer Part Num: ERJ-2GEJ221X; Num Pins: 2; Price: 0; RoHS Compliant: RoHS Compliant
R104 = RESISTOR: RES, 220 OHMS, 5%, 1/16W, 0402; Item Num: P02-14107R; Manufacturer: Panasonic; Manufacturer Part Num: ERJ-2GEJ221X; Num Pins: 2; Part Class: Resistors; Price: 0; RoHS Compliant: RoHS Compliant
R105 = RESISTOR: RES,10.0K OHMS,1.0%,1/16W, 0402; Item Num: P02-11364R; Manufacturer: Panasonic; Manufacturer Part Num: ERJ-2RKF1002X; Num Pins: 2; Price: 0; RoHS Compliant: RoHS Compliant
R5270 R5283 = RESISTOR: RES ZERO OHM 1/16W 5% 0402 SMD; Item Num: P02-14020R; Manufacturer: Panasonic; Manufacturer Part Num: ERJ-2GE0R00X; Num Pins: 2; Price: 0; RoHS Compliant: RoHS Compliant
R5271 = RESISTOR: RES,4.70K OHMS,1.0%,1/16W,0402; Item Num: P02-11384R; Manufacturer: Vishay; Manufacturer Part Num: CRCW04024K70FKED; Num Pins: 2; Part Class: Resistors; RoHS Compliant: RoHS Compliant
U9 = FT232R_2: IC - FTDI USB TO SERIAL UART INTERFACE, 32QFN; Item Num: P01-17819R; Manufacturer: FTDI; Manufacturer Part Num: FT232RQ-REEL; Num Pins: 32; RoHS Compliant: RoHS Compliant
U10 = TPD4S012DRYR: DIODE - HIGH SPEED, OTG, CHARGER USB ESD SOLUTION, 4CH, DRY; Item Num: P08-20820R; Manufacturer: Texas Instruments; Num Pins: 6; RoHS Compliant: RoHS Compliant
U63 = SN74AUP1G126DCK: IC - LOW-POWER SINGLE BUS BUFFER GATE WITH 3-STATE OUTPUT 3.6-V I/O TOLERANT; Item Num: P01-18133R; Manufacturer: Texas Instruments; Manufacturer Part Num: SN74AUP1G126DCKT
U64 U65 = SN74AUP1G17DCK: IC - SINGLE SCHMITT-TRIGGER BUFFER, 1.8/2.5/3.3V in, 3.3V CMOS out; Item Num: P01-18132R; Manufacturer: Texas Instruments
C954 C955 = CAP: SMD/SMT 10uF 10% 16Volts  0805; Item Num: P03-17702R; LIFECYCLE_PHASE: Active; Manufacturer: TDK Electronics; Manufacturer Part Num: C2012X5R1C106K085AC; RoHS Compliant: RoHS Compliant
C956 C957 = CAP: CAP - 0.1UF 0402 25V X7R; Item Num: P03-17618R; Manufacturer: TDK Electronics; Manufacturer Part Num: C1005X7R1E104M; Tolerance: +/-20%; Voltage: 25V
J8 = 2-767004-2: 38PIN MICTOR HEADER; Item Num: P23-08655R; Manufacturer: AMP/Tyco (Tyco Electronics Corporation); Mfr Code: AMTY; Price: 11.22; RoHS Compliant: RoHS Compliant
S1 S2 = TS-A02SA-2-S100_0: SWITCH - PUSH BUTTON 6.0X3.5MM SND; Item Num: P23-38485R; Lead Free Status: Yes; Manufacturer: Wurth Elektroniks; Manufacturer Part Num: 434121043816; Num Pins: 2; Part Class: Switches; RoHS Compliant: Yes
Y2 = OSC_ALT: OSC - CLOCK OSCILLATOR, 25MHZ, +/-50PPM, 1.8V, SMD; Item Num: P13-27249R; Manufacturer: Silicon Labs Inc.; Manufacturer Part Num: 510KBA25M0000BAG
C896 = CAP: CAP - CERAMIC, 10UF, 10%, X5R, 25V, 1206; Item Num: P03-15063R; Manufacturer: Murata; Manufacturer Part Num: GRM31CR61E106KA12; RoHS Compliant: RoHS Compliant
C900 C903 = CAP: CAP - CER 47UF 10V 20% X5R 1206; Dielectric: X5R; Item Num: P03-17644R; Manufacturer: TDK Electronics; Manufacturer Part Num: C3216X5R1A476M160AB; RATED_VOLTAGE: 6.3v; RoHS Compliant: Yes; Tolerance: 20%; Working Voltage: 6.3V
C921 C922 = CAP: CAP - CER, 10NF, 50V, +/-10%, X7R, 0402 SMD; Dielectric: X5R; Item Num: P03-16318R; Manufacturer: Murata; Manufacturer Part Num: GRM155R71H103KA88D; Price: 0.07; RoHS Compliant: RoHS Compliant
J11-J13 = mounting_hole
R456 = RESISTOR_0402: RES 13.3K OHM 1/16W 1.0% 0402 SMD; Manufacturer: Vishay; Manufacturer Part Num: CRCW040213K3FKED; item Num: P02-14487R
R667 = Resistor,_0402: RES 324K OHM 1/10W 1% 0402 SMD; Item Num: P02-16733R; Manufacturer: Panasonic; Manufacturer Part Num: ERJ-2RKF3243X
R669 = RESISTOR_0402: RES,8.25K OHMS,1.0%,1/16W,0402; Manufacturer: Panasonic; Manufacturer Part Num: ERJ-2RKF8251X; item Num: P02-11425R
U15 = LTM4622EV: REG - DUAL 2.5A OR SINGLE 5A STEP-DOWN DC/DC uMODULE REGULATOR; Item Num: P05-18786R; Manufacturer: Linear Technology; Manufacturer Part Num: LTM4622EY#PBF

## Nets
GND: C1.2 C2.1 C3.2 C4.1 C5.2 C6.2 C7.2 C8.2 C11.2 C13.1 C15.2 C17.1 C18.2 C20.1 C23.2 C25.1 C26.2 C28.2 C29.2 C31.1 C32.2 C33.1 C34.2 C35.1 C36.1 C37.1 C38.1 C39.2 C40.2 C41.2 C42.2 C43.1 C44.1 C45.1 C46.1 C47.1 C48.2 C53.2 C54.2 C55.1 C56.2 C57.1 C58.2 C59.1 C60.2 C61.1 C62.1 C63.1 C896.2 C900.1 C903.1 C909.2 C914.2 C915.2 C916.2 C919.2 C920.2 C921.2 C922.2 C924.1 C925.1 C927.1 C928.2 C929.1 C931.1 C932.1 C933.1 C934.1 C935.1 C936.1 C937.1 C938.1 C939.1 C940.1 C943.1 C944.2 C945.2 C946.2 C953.1 C954.2 C955.2 C956.2 C957.2 C958.2 C959.2 C960.1 C961.1 C962.1 C963.1 C964.1 C965.2 D1.3(A) D2.3(A) D3.3(A) J1.61 J1.62 J1.63 J1.64 J2.3 J3.18(GND_TAB) J3.19(GND_TAB) J4.5(GND) J5.6(VSS) J5.9(CAGE) J5.10(CAGE) J5.11(CAGE) J5.12(CAGE) J7.5(SHIELD) J8.5(GND) J8.16(TD7) J8.18(TD6) J8.20(TD5) J8.22(TD4) J8.23(TD15) J8.24(TD3) J8.25(TD14) J8.26(TD2) J8.27(TD13) J8.28(TD1) J8.29(TD12) J8.31(TD11) J8.33(TD10) J8.35(TD9) J8.37(TD8) J8.38(TD0) J8.39(GND1) J8.40(GND2) J8.41(GND3) J8.42(GND4) J8.43(GND5) J10.2 J11.1 J12.1 J13.1 Q1.2(SOURCE) Q2.2(SOURCE) Q3.2(SOURCE) Q4.2(SOURCE) Q5.2(SOURCE) Q6.2(SOURCE) Q7.2(SOURCE) R1.2 R17.2 R19.2 R23.2 R26.2 R28.2 R30.2 R32.2 R34.2 R36.2 R38.2 R39.1 R42.2 R45.2 R63.1 R78.1 R101.2 R106.2 R107.1 R109.1 R113.1 R114.1 R116.1 R612.2 R667.1 R668.1 R670.1 R698.1 R5266.2 R5269.2 R5275.2 R5276.1 R5285.2 S1.1 S2.1 U1.29(VSS) U1.49(P_GND) U3.8(GND) U3.9(GND_PAD) U4.33(GND_FLAG) U5.1(GND) U6.B1(GND) U9.4(GND1) U9.17(GND2) U9.20(GND3) U9.24(AGND) U9.26(TEST) U9.33(EPAD_GND) U10.4(GND) U15.B5(GND3) U15.C1(GND1) U15.C2(GND2) U15.D5(GND4) U62.5(GND) U62.11(EPAD) U63.3(GND) U64.3(GND) U65.3(GND) U68.3(GND) U69.3(GND) U70.3(GND) Y1.2 Y1.4 Y2.2(GND) Y3.2(GND)
VCC_3.3V: C48.1 C900.2 C924.2 C928.1 L1.1 R9.1 R16.1 R47.1 R126.1 R127.1 R129.1 R5262.2 R5308.1 U6.A2(Vin) U15.D1(VOUT1_1) U15.E1(VOUT1_2) U62.9(VIN2) U62.10(VIN1)
VCC_5V: C32.1 C903.2 U3.5(IN) U15.A1(VOUT2_1) U15.B1(VOUT2_2)
VCC_12V: C3.1 C4.2 C896.1 C959.1 J1.1 J1.60 U15.A2(VIN1) U15.B3(VIN3) U15.D3(VIN4) U15.E2(VIN2)
VCCIO_HPS: C1.1 C2.2 C45.2 C909.1 C946.1 C954.1 C956.1 C957.1 C958.1 C960.2 C961.2 C962.2 C963.2 J1.2 J1.59 L2.1 R4.1 R6.1 R7.1 R10.1 R44.1 R46.1 R79.1 R80.1 R81.1 R82.1 R83.1 R84.1 R110.2 R111.2 R112.2 R115.1 R125.2 R128.2 R675.1 R686.1 R687.1 R688.1 R689.1 R690.1 R691.1 R692.2 R693.2 R694.1 R695.1 R696.1 R697.1 R5304.1 R5305.1 R5306.2 R5307.2 R5309.1 U5.2(Vref_A) U63.5(VCC) U68.5(VCC) U69.5(VCC) U70.5(VCC)
ACTIVITY_LED: J3.13(YK) L9.2
CARD_PRSTn: J1.52 R1.1
CLK125_NDO_LED_MODE: R37.2 R38.1 U1.41(CLK125_NDO_LED_MODE)
CT0: C5.1 J3.12(CT0)
CT1: C6.1 J3.6(CT1)
CT2: C7.1 J3.1(CT2)
CT3: C8.1 J3.7(CT3)
DC_PGOOD: J1.54 R671.1 U15.B4(PGOOD2) U15.D4(PGOOD1)
DIP_1: J10.1 R5284.2 R5285.1 U63.1(OE)
E_RX_CLK: R8.1 R35.2 R36.1 U1.35(RX_CLK_PHYAD2)
E_RX_DV: R11.1 R33.2 R34.1 U1.33(RX_DV_CLK125_EN)
E_RXD0: R12.1 R31.2 R32.1 U1.32(RXD0_MODE0)
E_RXD1: R13.1 R29.2 R30.1 U1.31(RXD1_MODE1)
E_RXD2: R14.1 R27.2 R28.1 U1.28(RXD2_MODE2)
E_RXD3: R15.1 R25.2 R26.1 U1.27(RXD3_MODE3)
EN: R5286.1 U5.20(EN)
ENET_1.2V_AVDDL: C23.1 C25.2 C931.2 L4.2 U1.4(AVDDL) U1.9(AVDDL)
ENET_1.2V_AVDLL_PLL: C18.1 C20.2 L3.2 U1.44(AVDDL_PLL)
ENET_1.2V_DVDDL: C29.1 C31.2 C932.2 C933.2 C934.2 C935.2 C936.2 L5.2 U1.14(DVDDL) U1.18(DVDDL) U1.23(DVDDL) U1.26(DVDDL) U1.30(DVDDL) U1.39(DVDDL)
ENET_1.8V_DVDDH: C15.1 C17.2 C938.2 C939.2 L2.2 R18.1 R22.1 R25.1 R27.1 R29.1 R31.1 R33.1 R35.1 R37.1 U1.16(DVDDH) U1.34(DVDDH) U1.40(DVDDH)
ENET_3.3V_AVDDH: C11.1 C13.2 C937.2 L1.2 U1.1(AVDDH) U1.12(AVDDH)
ENET_GTX_CLK: J1.15 R5311.2
ENET_INTn: J1.27 R10.2 U1.38(INT_N/PME_N2)
ENET_LED1: Q6.1(GATE) R22.2 R23.1 U1.17(LED1_PHYAD0/PME_N1)
ENET_LED2: Q4.1(GATE) R18.2 R19.1 U1.15(LED2_PHYAD1)
ENET_MDC: J1.50 R4.2 U1.36(MDC)
ENET_MDIO: J1.49 R6.2 U1.37(MDIO)
ENET_RSET: R17.1 U1.48(ISET)
ENET_RSTn: R5287.2 U1.42(RESET_N)
ENET_RX_CLK: J1.17 R8.2
ENET_RX_DV: J1.18 R11.2
ENET_RXD0: J1.21 R12.2
ENET_RXD1: J1.22 R13.2
ENET_RXD2: J1.25 R14.2
ENET_RXD3: J1.26 R15.2
ENET_TX_EN: J1.16 U1.25(TX_EN)
ENET_TXD0: J1.19 U1.19(TXD0)
ENET_TXD1: J1.20 U1.20(TXD1)
ENET_TXD2: J1.23 U1.21(TXD2)
ENET_TXD3: J1.24 U1.22(TXD3)
ENET_VDD1.2V: C26.1 C28.1 C930.2 L3.1 L4.1 L5.1 R699.1 R5265.2 U62.1(VOUT1) U62.2(VOUT2)
ENET_XI: R21.2 U1.46(XI)
FPGA_JTAG_TCK: J1.55 R117.1 R693.1
FPGA_JTAG_TDI: J1.56 R121.1 R681.1 R686.2
FPGA_JTAG_TDO: J1.58 R123.1 R688.2
FPGA_JTAG_TMS: J1.57 R119.1 R682.1 R687.2
FT232R_3V3OUT: C55.2 C56.1 R97.1 U9.16(3V3OUT)
FT232R_RXD: U9.2(RXD) U65.4(Y)
FT232R_TXD: U9.30(TXD) U63.2(A)
FT232R_VCCIO: C57.2 C58.1 C919.1 C944.1 C945.1 D4.A(ANODE) D5.A(ANODE) R97.2 R105.2 R5271.1 R5284.1 U9.1(VCCIO) U64.5(VCC) U65.5(VCC)
HPS_JTAG_TCK: J1.35 R118.1 R692.1
HPS_JTAG_TDI: J1.38 R122.1 R689.2
HPS_JTAG_TDO: J1.37 R124.1 R691.2
HPS_JTAG_TMS: J1.36 R120.1 R690.2
HPS_LED0: J1.47 Q1.1(GATE) R681.2
HPS_LED1: J1.46 Q3.1(GATE) R682.2
HPS_LED2: J1.48 Q2.1(GATE)
HPS_OSC_CLK: J1.45 R5291.2
HPS_OSC_CLK_1.8V: C953.2 C955.1 R131.1 R5309.2 Y2.4(VCC)
HPS_PB0: J1.31 U69.4(Y)
HPS_PB1: J1.32 U70.4(Y)
HPS_RESETn: J1.53 R7.2 R683.1
HPS_RESETn_1: R685.1 U68.2(A)
I2C1_SCL: J1.34 J2.1 R695.2
I2C1_SDA: J1.33 J2.2 R694.2
INTVCC: R671.2 U15.C3(INTVCC)
LDO_O: U1.43(LDO_O)
LINK_LED: J3.17(GK) L10.2
LOGIC0A: J8.30(Logic0A) R113.2
LOGIC0B: J8.32(Logic0B) R114.2
LOGIC1: J8.34(LOGIC1) R115.2
MDI_HPS_N0: J3.10(TD0_N) U1.3(TXRXM_A)
MDI_HPS_N1: J3.5(TD1_N) U1.6(TXRXM_B)
MDI_HPS_N2: J3.2(TD2_N) U1.8(TXRXM_C)
MDI_HPS_N3: J3.9(TD3_N) U1.11(TXRXM_D)
MDI_HPS_P0: J3.11(TD0_P) U1.2(TXRXP_A)
MDI_HPS_P1: J3.4(TD1_P) U1.5(TXRXP_B)
MDI_HPS_P2: J3.3(TD2_P) U1.7(TXRXP_C)
MDI_HPS_P3: J3.8(TD3_P) U1.10(TXRXP_D)
MICRO_USB_PGND: C940.2 J4.6(SHELL1) J4.7(SHELL2) J4.8(SHELL3) J4.9(SHELL4) R5266.1
MICTOR_JTAG_TCK: R117.2 R118.2 R5301.1
MICTOR_JTAG_TDI: R121.2 R122.2 R5303.1
MICTOR_JTAG_TDO: J8.11(TDO/SWO) R123.2 R124.2
MICTOR_JTAG_TMS: R119.2 R120.2 R5302.1
MICTOR_JTAG_TRSTn: J8.21(nTRST) R112.1
MICTOR_PWR1: J8.12(VTREF) R110.1
MICTOR_SRSTn: J8.9(nSRST) R684.2
MINI_USB_PGND: C943.2 J7.6(SHIELD2) J7.7(SHIELD3) R5269.1
PB_SW0: C62.2 R125.1 S1.2 U69.2(A)
PB_SW1: C63.2 R128.1 S2.2 U70.2(A)
PHY_25M_3.3V: C925.2 C927.2 R20.1 R5308.2 Y3.4(VCC)
PWN_EN: J1.51 R698.2 R5307.1 U15.B2(RUN2) U15.D2(RUN1)
PWR_ENA: R105.1 U9.11(CBUS3)
SD_3.3V: C42.1 C43.2 C44.2 C47.2 J5.4(VDD) R66.2 R67.1 U6.A1(Vout)
SD_CLK: J1.41 R79.2 U5.10(A8)
SD_CLK_3.3V: D3.1(K1) J5.5(CLK) R76.1 U5.11(B8)
SD_CMD: J1.40 R80.2 U5.9(A7)
SD_CMD_3.3V: D3.2(K2) J5.3(CMD) R75.1 U5.12(B7)
SD_DATA0: J1.39 R81.2 U5.5(A3)
SD_DATA0_3.3V: D2.1(K1) J5.7(DAT0) R70.1 U5.16(B3)
SD_DATA1: J1.42 R82.2 U5.6(A4)
SD_DATA1_3.3V: D2.2(K2) J5.8(DAT1) R72.1 U5.15(B4)
SD_DATA2: J1.43 R83.2 U5.7(A5)
SD_DATA2_3.3V: D1.1(K1) J5.1(DAT2) R73.1 U5.14(B5)
SD_DATA3: J1.44 R84.2 U5.8(A6)
SD_DATA3_3.3V: D1.2(K2) J5.2(CD/DAT3) R74.1 R78.2 U5.13(B6)
SD_RSTn: R5289.2 R5306.1 U6.B2(ON)
TRACECTL: J8.36(TRACECTL) R116.2
UART_RESETn: R5270.2 R5271.2 U9.18(~{RESET})
UART_RSTn: R5290.2 U64.2(A)
UART_RX: J1.30 R696.2 R5283.2 R5300.1
UART_RX_LED: R104.1 U9.21(CBUS1)
UART_TX: J1.29 R697.2 R5283.1 U65.2(A)
UART_TX_LED: R103.1 U9.22(CBUS0)
USB_5V: C33.2 C39.1 J4.1(VBUS) R54.1 U3.4(OUT)
USB_CLK: J1.3 R59.1
USB_CLKR: R59.2 U4.1(CLKOUT)
USB_CPEN: R45.1 U3.7(ON) U4.17(CPEN)
USB_D_N: J4.2(D-) U4.19(DM)
USB_D_P: J4.3(D+) U4.18(DP)
USB_DATA0: J1.6 R5292.1
USB_DATA1: J1.7 R5293.1
USB_DATA2: J1.9 R5294.1
USB_DATA3: J1.10 R5295.1
USB_DATA4: J1.11 R5296.1
USB_DATA5: J1.12 R5297.1
USB_DATA6: J1.13 R5298.1
USB_DATA7: J1.14 R5299.1
USB_DIR: J1.5 R61.1
USB_DIRR: R61.2 U4.31(DIR)
USB_ID: J4.4(ID) U4.23(ID)
USB_NXT: J1.8 R60.1
USB_NXTR: R60.2 U4.2(NXT)
USB_RBIAS: R63.2 U4.24(RBIAS)
USB_RSTn: R5288.2 U4.27(RESET)
USB_STP: J1.4 U4.29(STP)
USB_UART_5V: C59.2 C60.1 L6.1 U9.19(VCC) U10.6(VBUS)
USB_UART_CON_5V: C61.2 C920.1 J7.1(VBUS) L6.2
USB_UART_DM: C53.1 J7.2(D-) U9.15(USBDM) U10.1(D+)
USB_UART_DP: C54.1 J7.3(D+) U9.14(USBDP) U10.2(D-)
USB_VBAT: C34.1 C35.2 C914.1 R47.2 U4.20(VDD3.3) U4.21(VBAT)
USB_VBUS: R54.2 U4.22(VBUS)
USB_VDD18: C36.2 C38.2 C916.1 R44.2 U4.28(VDD1.8) U4.30(VDD1.8)
USB_VDDIO: C37.2 C915.1 R46.2 U4.8(REFSEL0) U4.11(REFSEL1) U4.14(REFSEL2) U4.32(VDDIO)
USB_VFlagn: J1.28 R675.2 U3.2(~{FLAG})
USB_XI: C41.1 R62.1 U4.26(REFCLK) Y1.1
USB_XO: C40.1 R62.2 U4.25(XO) Y1.3
VREF_B: C46.2 R66.1 R5286.2 U5.19(Vref_B)
N134005839: J7.4(GND) R101.1
N134005899: D4.C(CATHODE) R103.2
N134005901: D5.C(CATHODE) R104.2
N134009559: R42.1 U3.3(SETI)
N134057943: R67.2 R70.2 R72.2 R73.2 R74.2 R75.2 R76.2
N134062955: J8.8(TRIGOUT) R107.2
N134063078: J8.14(Vsupply) R111.1
N134063167: J8.10(NC) R109.2
N134106197: D6.A(ANODE) R126.2
N134106201: D6.C(CATHODE) Q1.3(DRAIN)
N134106389: D8.A(ANODE) R129.2
N134106393: D8.C(CATHODE) Q3.3(DRAIN)
N134106834: D7.A(ANODE) R127.2
N134106836: D7.C(CATHODE) Q2.3(DRAIN)
N134121389: R131.2 Y2.1(EN)
N134121395: R5291.1 Y2.3(OUT)
N134242750: R667.2 U15.C4(FREQ)
N134242873: R612.1 U15.C5(SYNC/MODE)
N134242878: C922.1 U15.A3(TRACK/SS2)
N134242888: C921.1 U15.E3(TRACK/SS1)
N134243679: R456.1 R668.2
N134244009: R669.2 U15.A4(FB2)
N134244011: R669.1 R670.2
N134244826: R456.2 U15.E4(FB1)
N134266858: R683.2 R684.1 R685.2
N134303911: R5262.1 U62.7(EN)
N134304469: C929.2 U62.6(SS)
N134306474: C930.1 R39.2 R699.2 U62.3(VFB)
N134306486: R5265.1 U62.4(POK)
N134320476: R5270.1 U64.4(Y)
N134322722: J8.13(RTCK) R5275.1
N134323149: J8.6(TRACECLK) R5276.2
N134323985: R5287.1 R5288.1 R5289.1 R5290.1 U68.4(Y)
N134337329: J8.7(TRIGIN) R106.1
N134344647: R5298.2 U4.10(DATA6)
N134344648: R5293.2 U4.4(DATA1)
N134344649: R5295.2 U4.6(DATA3)
N134344650: R5297.2 U4.9(DATA5)
N134344651: R5292.2 U4.3(DATA0)
N134344652: R5299.2 U4.13(DATA7)
N134344653: R5294.2 U4.5(DATA2)
N134344654: R5296.2 U4.7(DATA4)
N134352854: R5300.2 U63.4(Y)
N134353275: J8.15(TCK) R5301.2
N134353287: J8.17(TMS) R5302.2
N134353299: J8.19(TDI) R5303.2
N134367002: Q4.3(DRAIN) Q5.1(GATE) R5304.2
N134368065: R20.2 Y3.1(EN)
N134368399: Q6.3(DRAIN) Q7.1(GATE) R5305.2
N134420239: L9.1 Q7.3(DRAIN)
N134420387: L10.1 Q5.3(DRAIN)
N134420624: C964.2 J3.16(GOA) R16.2
N134420965: C965.1 J3.14(YA) R9.2
N134431006: R5311.1 U1.24(GTX_CLK)
N134431314: R21.1 Y3.3(OUT)

Not connected (* = marked no-connect by the designer): J3 15(OK)*; J8 1(NC1)* 2(NC3)* 3(NC2)* 4(NC4)*; U1 13(NC)* 45(XO)* 47(NC1)*; U3 1(NC1)* 6(NC2)*; U4 12(NC)* 15(SPK_L)* 16(SPK_r)*; U5 3(A1)* 4(A2)* 17(B2)* 18(B1)*; U9 3(~{RI})* 5(NC3)* 6(~{DSR})* 7(~{DCD})* 8(~{CTS})* 9(CBUS4)* 10(CBUS2)* 12(NC4)* 13(NC5)* 23(NC2)* 25(NC1)* 27(OSCI)* 28(OSCO)* 29(NC6)* 31(~{DTR})* 32(~{RTS})*; U10 3(ID)* 5(NC)*; U15 A5(COMP2)* E5(COMP1)*; U62 8(NC)*; U64 1(NC)*; U65 1(NC)*; U68 1(NC)*; U69 1(NC)*; U70 1(NC)*

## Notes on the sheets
sheet 1
- NOTES:
- 1.
- Project Drawing Numbers:
       Raw PCB
       Gerber Files
       PCB Design Files
       Assembly Drawing
       Fab Drawing
       Schematic Drawing
       PCB Film
       Bill of Materials
       Schematic Design Files
       Functional Specification
       PCB Layout Guidelines
       Assembly Rework
- 100-0330632-A2
  110-0330632-A2
  120-0330632-A2
  130-0330632-A2
  140-0330632-A2
  150-0330632-A2
  160-0330632-A2
  170-0330632-A2
  180-0330632-A2
  210-0330632-A2
  220-0330632-A2
  320-0330632-A2
- Pre-Release Schematic
        DO NOT COPY
- REV
- DATE
- PAGE
- DESCRIPTION
- A
- initial schematic release
- 2.
- This board was designd for Stratix 10 SoC Development Kit.
- PAGE
- DESCRIPTION
- 1
- Title
- 2
- IO48 Connector
- 3
- RGMII Ethernet
- 4
- USB2.0 OTG
- 5
- Micro SD Card
- 6
- USB2UART
- 7
- Mictor, PBs, LEDs
- 8
- Power
- PAGE
- DESCRIPTION
- 1
- Page Description, revision history
- 2
- FMC connector A
- 3
- FMC connector B
sheet 2
- IO48_GPIO0_USB0_CLK
- IO48_GPIO1_USB0_STP
- IO48_GPIO2_USB0_DIR
- IO48_GPIO3_USB0_DATA0
- IO48_GPIO4_USB0_DATA1
- IO48_GPIO5_USB0_NXT
- IO48_GPIO6_USB0_DATA2
- IO48_GPIO7_USB0_DATA3
- IO48_GPIO8_USB0_DATA4
- IO48_GPIO9_USB0_DATA5
- IO48_GPIO10_USB0_DATA6
- IO48_GPIO12_EMAC0_TX_CLK
- IO48_GPIO11_USB0_DATA7
- IO48_GPIO13_EMAC0_TX_CTL
- IO48_GPIO14_EMAC0_RX_CLK
- IO48_GPIO15_EMAC0_RX_CTL
- IO48_GPIO16_EMAC0_TXD0
- IO48_GPIO17_EMAC0_TXD1
- IO48_GPIO18_EMAC0_RXD0
- IO48_GPIO19_EMAC0_RXD1
- IO48_GPIO20_EMAC0_TXD2
- IO48_GPIO21_EMAC0_TXD3
- IO48_GPIO22_EMAC0_RXD2
- IO48_GPIO24_GPIO1_IO0
- IO48_GPIO23_EMAC0_RXD3
- IO48_GPIO25_GPIO1_IO1
- IO48_GPIO26_UART0_TX
- IO48_GPIO27_UART0_RX
- IO48_GPIO28_GPIO1_IO4
- IO48_GPIO29_GPIO1_IO5
- IO48_GPIO30_I2C1_SDA
- IO48_GPIO31_I2C1_SCL
- IO48_GPIO32_JTAG_TCK
- IO48_GPIO33_JTAG_TMS
- IO48_GPIO34_JTAG_TDO
- IO48_GPIO35_JTAG_TDI
- IO48_GPIO36_SDMMC_DATA0
- IO48_GPIO38_SDMMC_CCLK
- IO48_GPIO37_SDMMC_CMD
- IO48_GPIO39_SDMMC_DATA1
- IO48_GPIO40_SDMMC_DATA2
- IO48_GPIO41_SDMMC_DATA3
- IO48_GPIO42_OSC_CLK
- IO48_GPIO43_GPIO1_IO19
- IO48_GPIO44_GPIO1_IO20
- IO48_GPIO45_GPIO1_IO21
- IO48_GPIO46_MDIO0_MDIO
- IO48_GPIO47_MDIO0_MDC
- MotherBoard:        QSH-030-01-C-D-A
  IO48 OOBE Card:  QTH-030-02-L-D-A
  Stack-up Height:     8mm
- Used in S10 Check out board
- Reset FPGA logic externally by HPS
- Update external watchdog for HP
- I2C Header
sheet 3
- 10/100/1000 Ethernet - HPS
- Ethernet Interface
- No Activity:  OFF
- Activity (RX, TX) : Blinking
- NAME
- Pin
- Value
- Description
- PHYAD2
- 35
- 1
- ID = b"100"
- On-Chip Termination Resistors for the Differential Pairs
- PHYAD1
- 15
- 0
- PHYAD0
- 17
- 0
- RGMII
  (10/100/1000 half-/full-duplex)
- MODE3
- 27
- 1
- MODE2
- 28
- 1
- MODE1
- 31
- 1
- MODE0
- 32
- 1
- Link OFF
- ClK125_EN
- 33
- 0
- No clockoutput from pin41
- Link ON
- LED_MODE
- 41
- 1
- single led
  mode
- Activity
- Link
- BOOT-STRAPS
- Place near KSZ9031RN PHY
- Use AVDDH supply for the crystal/clock pins (XI, XO)
- Ethernet 1.2V LDO
- 250mA Max.
- PUS: AVDDH/DVDDH before 1.2V core
sheet 4
- USB 2.0 OTG Port
- USB Current Limit
- Current limit for Rseti of 137k is 1.01A
- Place C39 near the USB connector
- VBUS Overvoltage Protection
- Place R63 as close as possible to USB3320
- The nominal voltage at RBIAS is 0.8V +/- 10%
- RESETB must be held low until the VDD18 and VDDIO supplies are stable
- ULPI Output Clock
- REFSEL[2:0] = 0X7,
  Reference Frequency = 24Mhz
sheet 5
- MicroSD Card
- Micro SD Card
- The B-side pullup resistors should
  be sized according to signal frequency and current limits
- IEC61000-4-2 (ESD): ± 20 kV (air / contact)
- ON Vih Threhold: 0.85V
- IEC61000-4-4 (EFT): ±50 A (5/50 ns)
- IEC61000-4-5 (surge): ±3 A (8/20 µs)
sheet 6
- OE=L
  A=X (Floating input allowed)
  Y=Z
- Debugging Loopback
  Pop R5283, short J10
- USB-UART Port
- WE 651005136421
sheet 7
- Mictor, LED, PushButton, CLK
- Notes:
  LED is ON when HPS_LEDx is high
  LED is OFF when HPS_LEDx is low
- 25MHz HPS CLK
sheet 8
- 3.3V/1A (Max.)
- 12V -> 5V/3.3V
- 5V/1.1A (Max.)
- 25V
